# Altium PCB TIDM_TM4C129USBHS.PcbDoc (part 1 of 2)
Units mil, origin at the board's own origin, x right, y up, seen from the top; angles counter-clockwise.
Board outline 3900 x 3450 mil, 4 copper layers (Component Side, Ground Plane, Power Plane, Solder Side), stack 59.6 mil thick; 136 components, 129 nets, 585 pads, 295 vias.
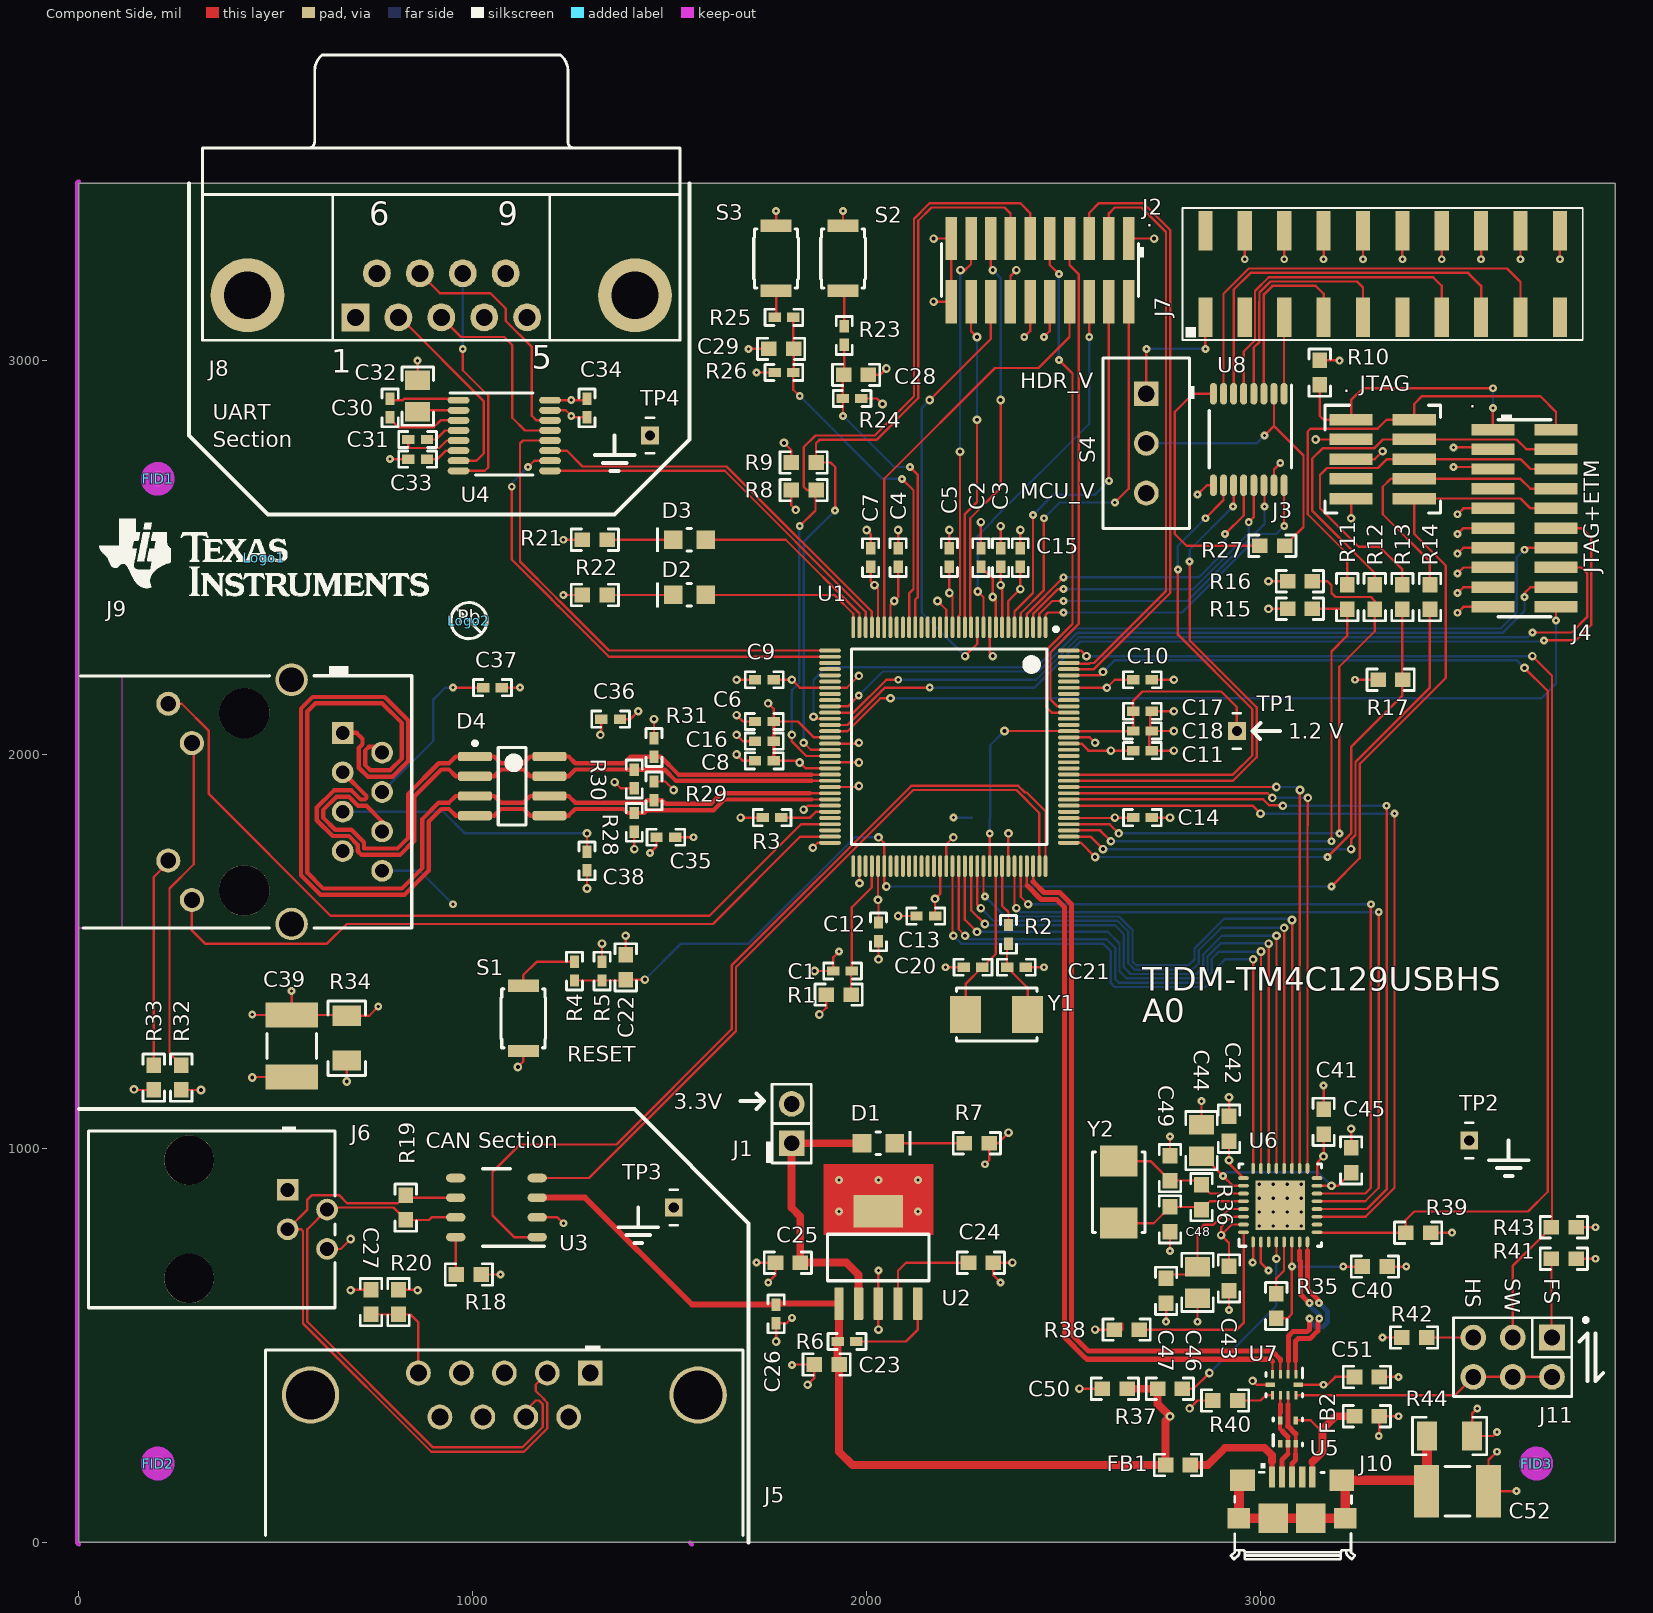
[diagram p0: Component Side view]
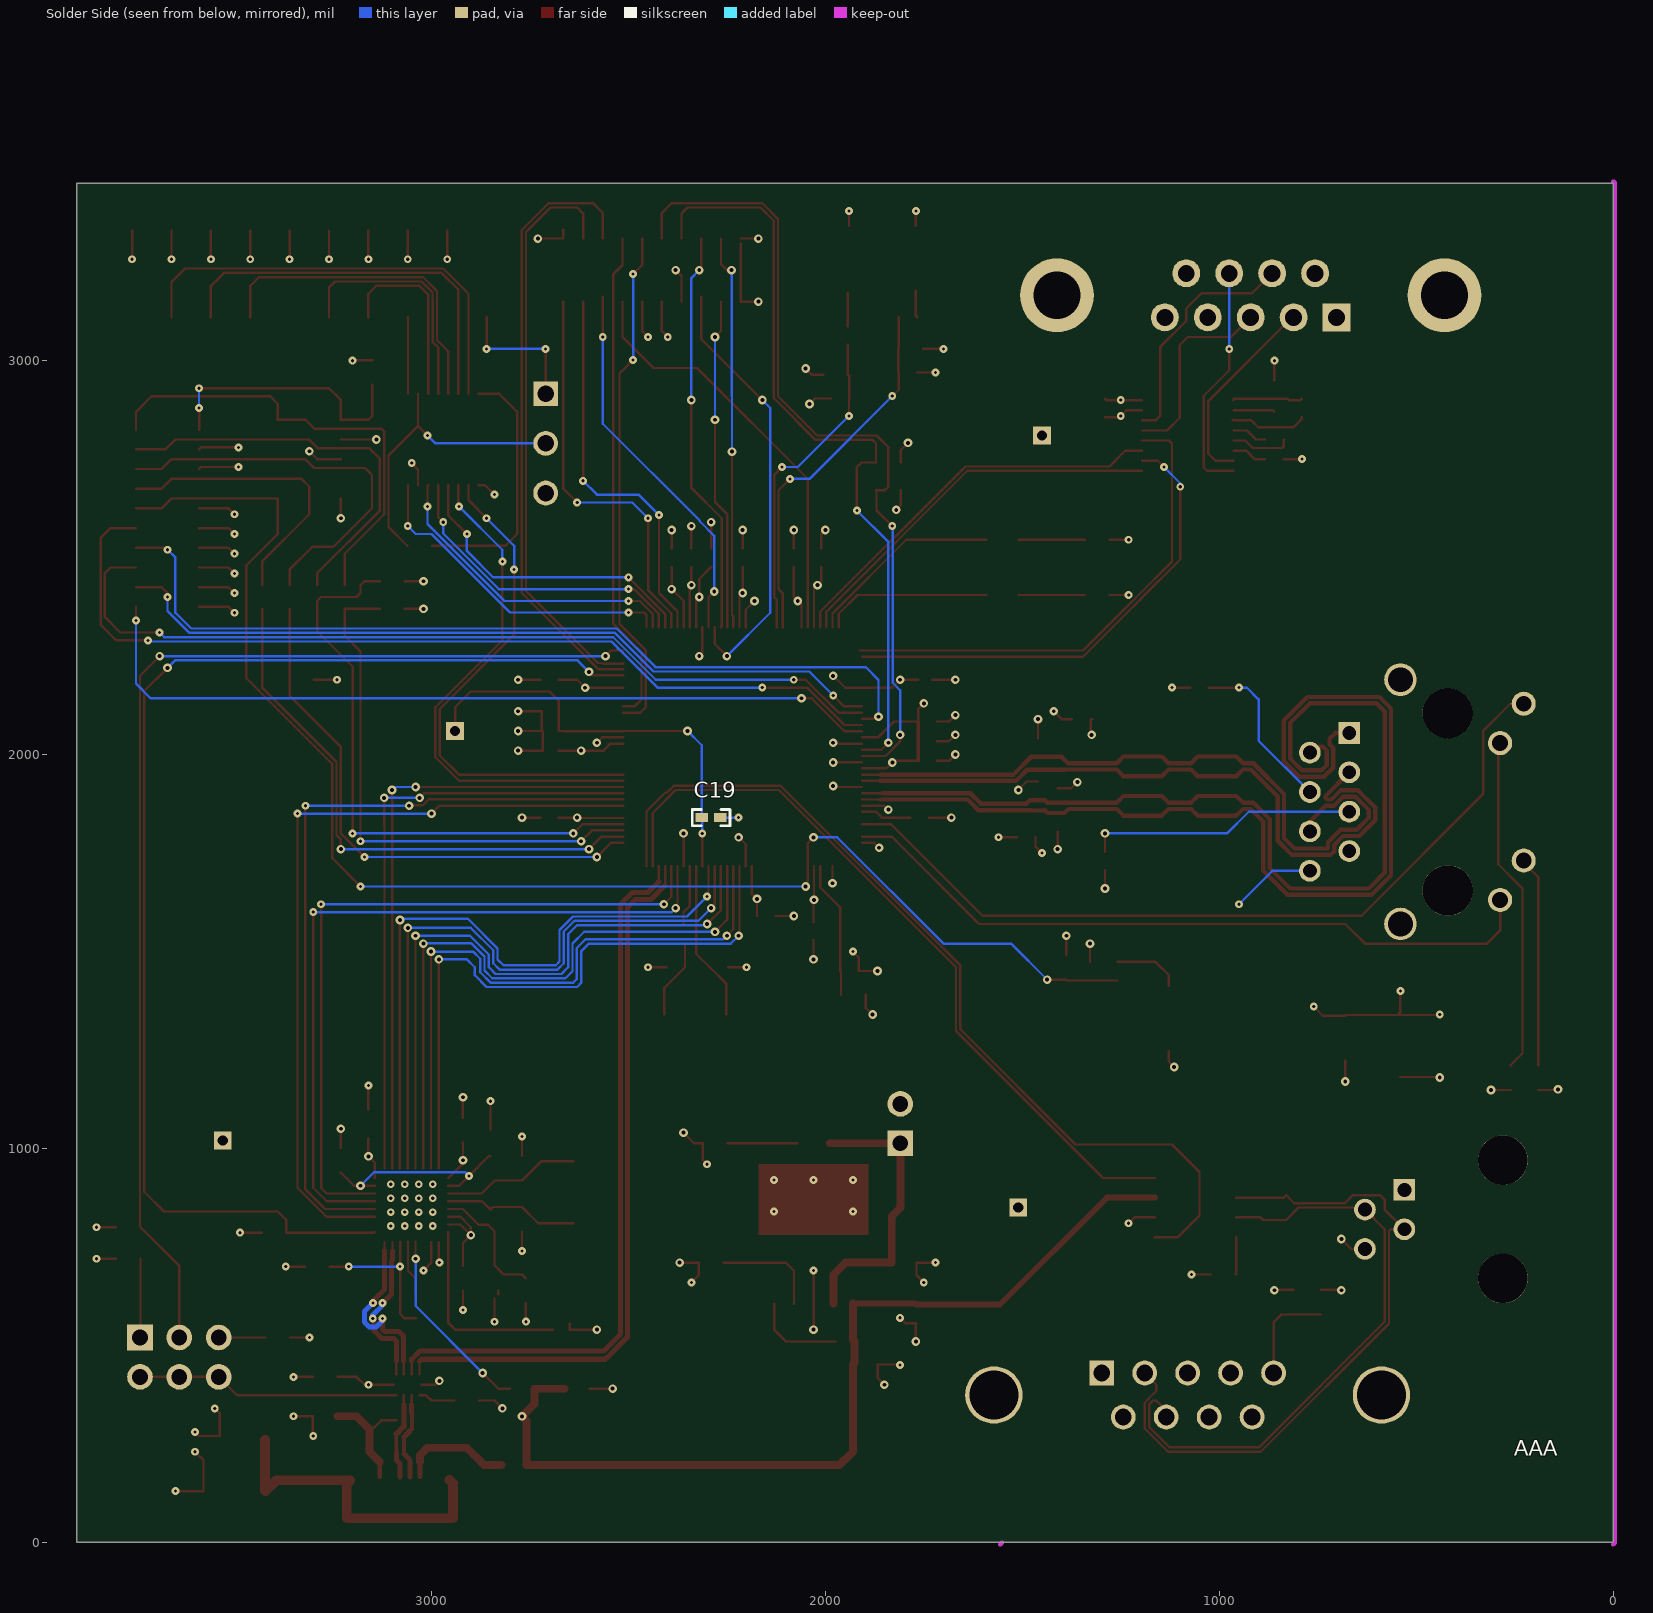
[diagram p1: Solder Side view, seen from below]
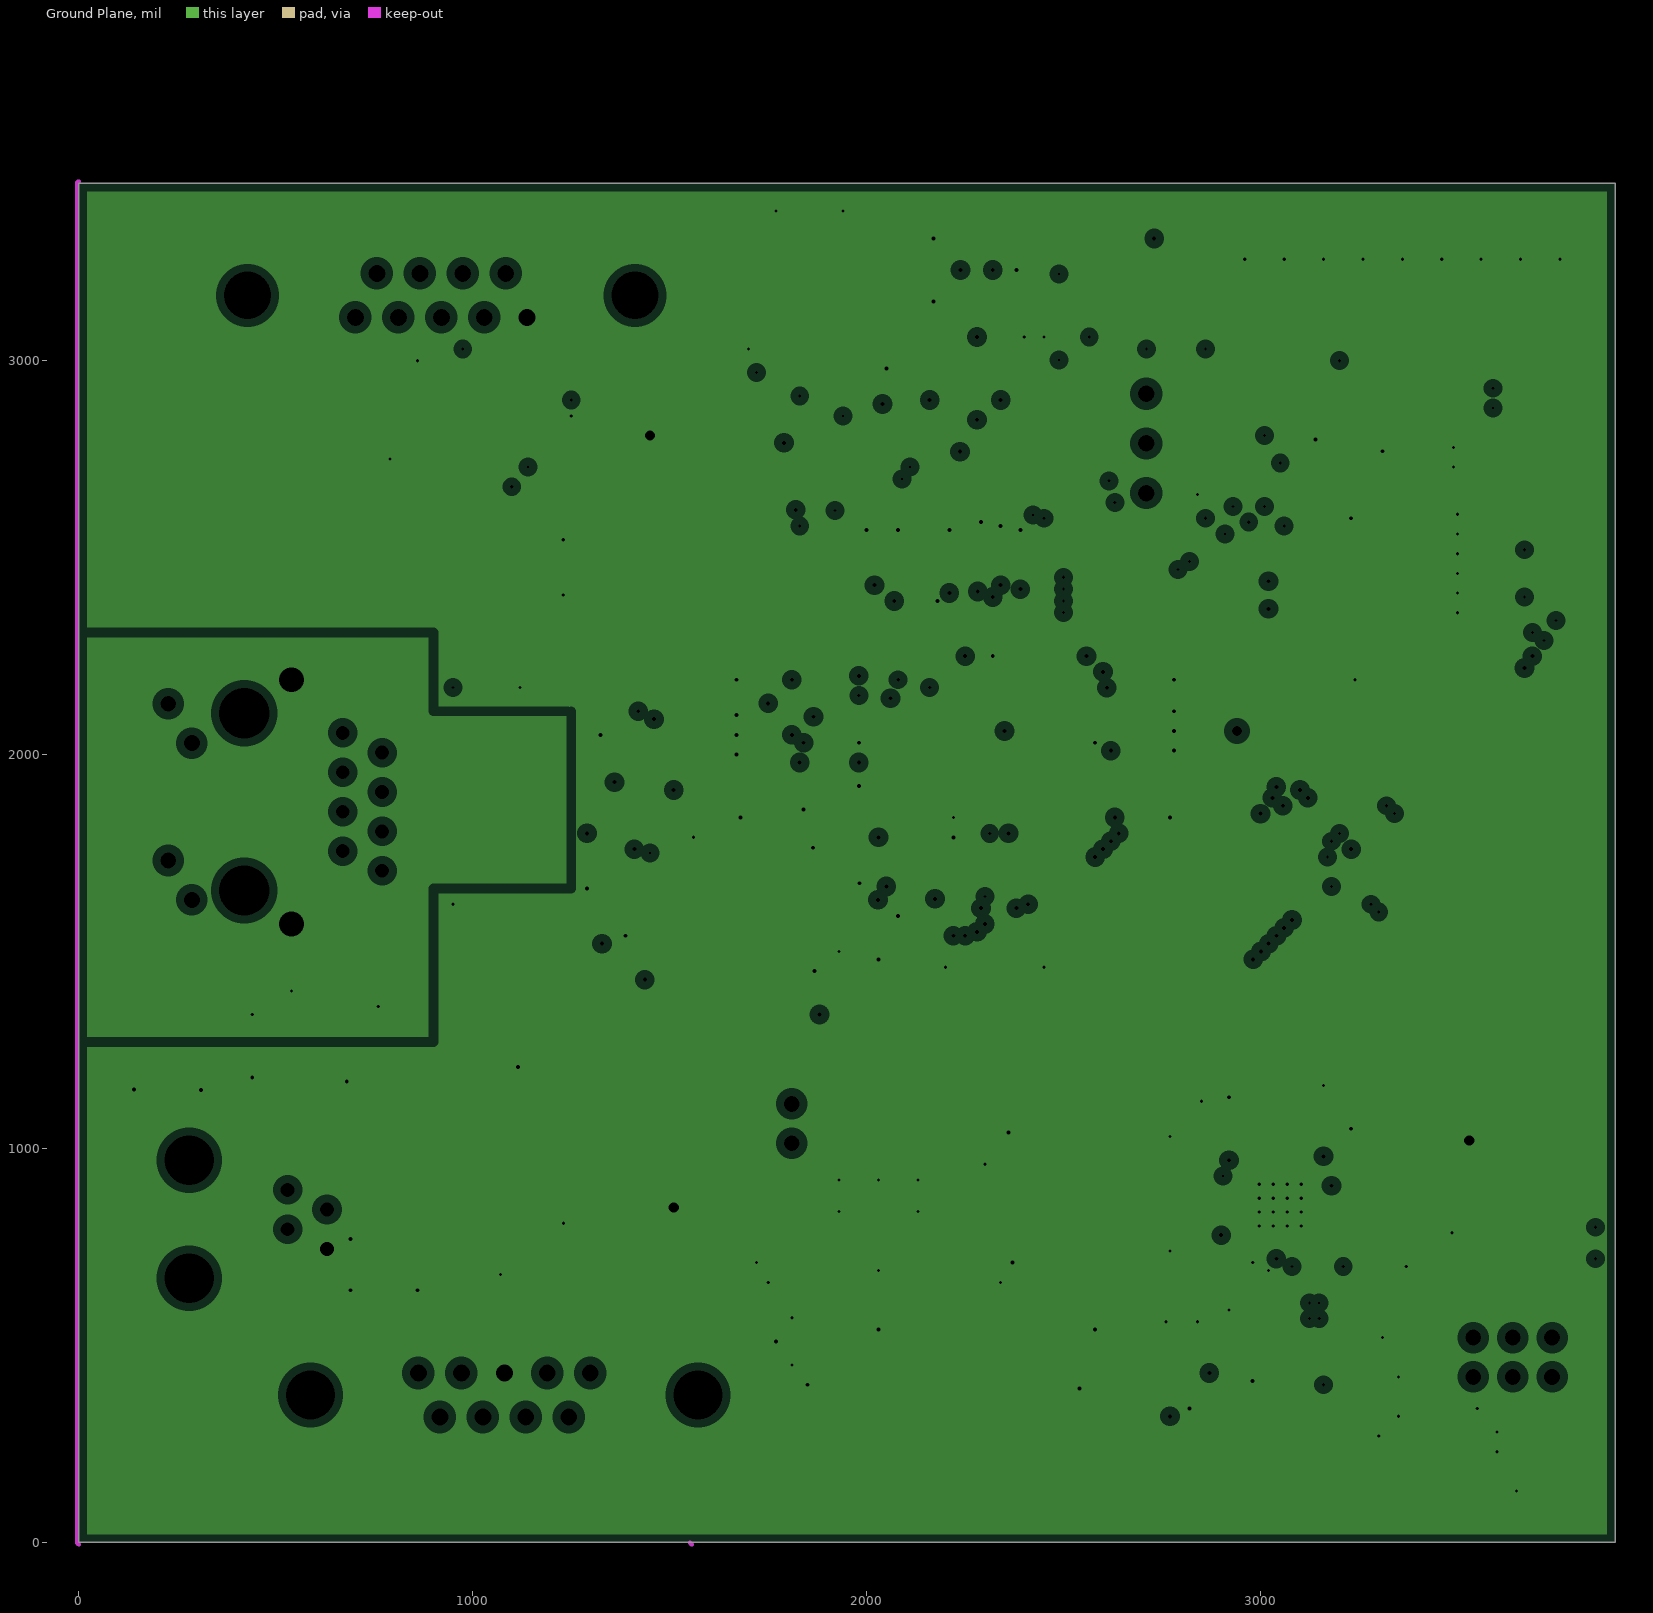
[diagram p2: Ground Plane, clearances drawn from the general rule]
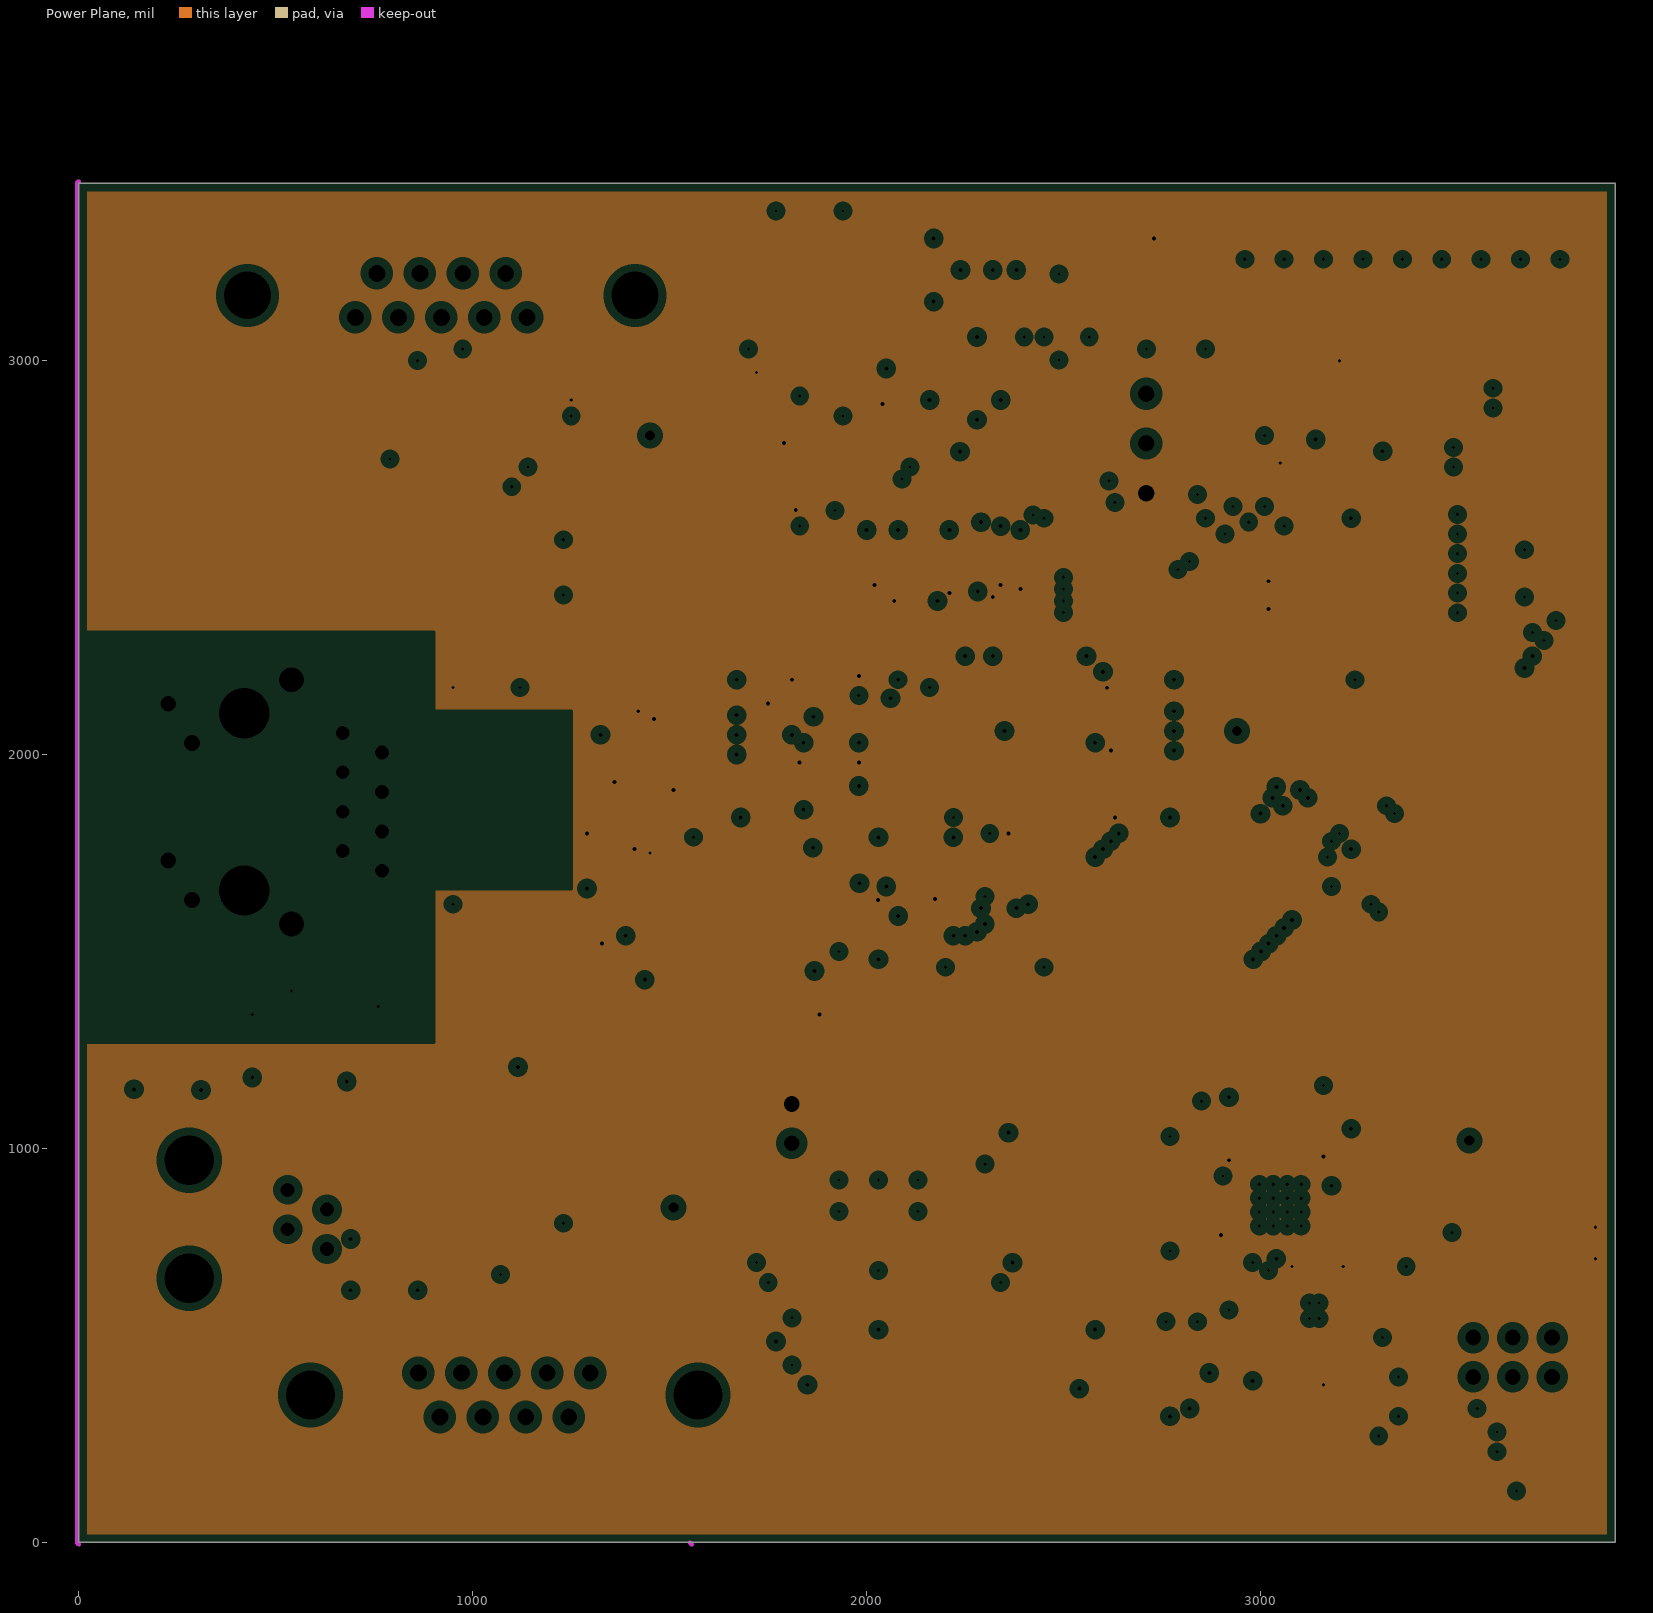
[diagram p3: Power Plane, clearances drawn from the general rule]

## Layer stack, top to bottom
Top Solder: solder mask 0.4, Solder Resist, Dk 3.5
Component Side: signal copper 1.4
Dielectric 1: core 13, FR-4, Dk 4.8
Ground Plane: plane copper 1.4, net (Multiple Nets)
Dielectric 3: prepreg 28, Dk 4.2
Power Plane: plane copper 1.4, net VCC_3P3
Dielectric 4: core 13, Dk 4.2
Solder Side: signal copper 1.4
Bottom Solder: solder mask 0.4, Solder Resist, Dk 3.5

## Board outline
0,0 0,3450 3900,3450 3900,0

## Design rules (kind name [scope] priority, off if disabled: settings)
AcuteAngle [All] p1: minimum=4.50000000000000E+0001 checktracksonly=FALSE
AssemblyTestPointUsage [All] p1: valid=2
Clearance Clearance_Pwr2GndVia [(IsVia AND (InNet('GND') OR InNet('VCC_3P3'))) vs (IsVia AND (InNet('GND') OR InNet('VCC_3P3')))] p1: gap=10
Clearance Clearance_Keepouts [((IsTrack Or IsArc) And Not InPoly) And IsFree and IsKeepOut vs ((IsTrack Or IsArc) And Not InPoly) And IsFree and IsKeepOut] p2: gap=0
Clearance Clearance_BoardEdge_MountingHoles [OnCopper and InComponentClass('Mounting Holes') vs IsKeepOut] p3: gap=40
Clearance Clearance_BoardEdge_Poly [OnCopper and InPoly vs IsKeepOut] p4: gap=25
Clearance Clearance_BoardEdge [OnCopper and Not InComponentClass('Logo') and not InComponentClass('FiducialMark') and not InRegion(1000,500,4000,800) and Not IsKeepout vs IsKeepOut] p5: gap=20
Clearance Clearance_Poly [InPolygon] p6: gap=10
Clearance [All] p7: gap=5
ComponentClearance ComponentClearance_MountingHoles_FiducialMarks [InComponentClass('Mounting Holes') vs InComponentClass('FiducialMark')] p1: gap=50 collisioncheckmode=3 verticalgap=10 showdistances=FALSE
ComponentClearance ComponentClearance_Shunt [InComponentClass('Header') vs InComponentClass('Shunt')] p2: gap=0 collisioncheckmode=3 verticalgap=0 showdistances=FALSE
ComponentClearance ComponentClearance_Logo [InComponentClass('Logo')] p3: gap=50 collisioncheckmode=3 verticalgap=10 showdistances=FALSE
ComponentClearance ComponentClearance_ScrewToNut [(HasFootprint('NY PMS 440 0025 PH')) vs (HasFootprint('Keystone_1902C'))] p4: gap=5 collisioncheckmode=3 verticalgap=10 showdistances=FALSE
ComponentClearance ComponentClearance_MountingHoles [InComponentClass('Mounting Holes')] p5: gap=250 collisioncheckmode=3 verticalgap=100000 showdistances=FALSE
ComponentClearance ComponentClearance_SmallPassives [HasFootprint('0201*') or HasFootprint('0402*') or HasFootprint('0508') or HasFootprint('0603*') or HasFootprint('0612') or HasFootprint('0805*') or HasFootprint('0815*') or HasFootprint('0830*') or HasFootprint('1206*') or HasFootprint('1210*') or HasFootprint('1808*') or HasFootprint('1812*') or HasFootprint('1825*') or HasFootprint('2010*') or HasFootprint('2220*') or HasFootprint('2225*') or HasFootprint('2512*') or HasFootprint('2728*') or HasFootprint('3518*') vs HasFootprint('0201*') or HasFootprint('0402*') or HasFootprint('0508') or HasFootprint('0603*') or HasFootprint('0612') or HasFootprint('0805*') or HasFootprint('0815*') or HasFootprint('0830*') or HasFootprint('1206*') or HasFootprint('1210*') or HasFootprint('1808*') or HasFootprint('1812*') or HasFootprint('1825*') or HasFootprint('2010*') or HasFootprint('2220*') or HasFootprint('2225*') or HasFootprint('2512*') or HasFootprint('2728*') or HasFootprint('3518*')] p6: gap=20 collisioncheckmode=3 verticalgap=10 showdistances=FALSE
ComponentClearance ComponentClearance_THtoSMT [IsThruComponent vs IsSMTComponent] p7: gap=40 collisioncheckmode=3 verticalgap=30 showdistances=FALSE
ComponentClearance ComponentClearance_THtoTH [IsThruComponent vs IsThruComponent] p8: gap=40 collisioncheckmode=3 verticalgap=30 showdistances=FALSE
ComponentClearance [All] p9: gap=40 collisioncheckmode=3 verticalgap=10 showdistances=FALSE
DiffPairsRouting DiffPairsRoutingUSB [(InNet('USBCONN_N') OR InNet('USBCONN_P') OR InNet('USBD_N') OR InNet('USBD_P') OR InNet('USBHS_N') OR InNet('USBHS_P'))] p1: maxlimit=50 minlimit=5 mostfreqgap=5 toplayer_minwidth=5 toplayer_maxwidth=14 toplayer_prefwidth=12.8 bottomlayer_minwidth=5 bottomlayer_maxwidth=14 bottomlayer_prefwidth=12.8 maxuncoupledlength=500
DiffPairsRouting DiffPairsRoutingEPHY [(InNet('EPHYRX_N') OR InNet('EPHYRX_P') OR InNet('EPHYtX_N') OR InNet('EPHYTX_P'))] p2: maxlimit=50 minlimit=5 mostfreqgap=5 toplayer_minwidth=6 toplayer_maxwidth=14 toplayer_prefwidth=11 bottomlayer_minwidth=6 bottomlayer_maxwidth=14 bottomlayer_prefwidth=11 maxuncoupledlength=500
FabricationTestPointUsage TestPointUsage [All] p1: valid=2 allowmultiple=FALSE
FabricationTestpoint Testpoint [All] p1: side=3 testpointundercomponent=TRUE minsize=40 maxsize=100 preferedsize=60 minholesize=0 maxholesize=40 preferedholesize=32 testpointgrid=1 allowsidetop=TRUE allowsidebottom=TRUE usegrid=TRUE gridtolerance=0.01
FanoutControl Fanout_LCC [IsLCC] p1: bgadir=Out bgaviamode=Centered fanoutstyle=Auto fanoutdirection=Alternating viagrid=1 // Fanout_LCC (Default Rule)
FanoutControl Fanout_BGA [IsBGA] p2: bgadir=Out bgaviamode=Centered fanoutstyle=Auto fanoutdirection=Alternating viagrid=1 // Fanout_BGA (Default Rule)
FanoutControl Fanout_Default [All] p4: bgadir=Out bgaviamode=Centered fanoutstyle=Auto fanoutdirection=Alternating viagrid=1 // Fanout_Default (Default Rule)
FanoutControl Fanout_Small [(CompPinCount < 5)] p5: bgadir=Out bgaviamode=Centered fanoutstyle=Auto fanoutdirection=OutThenIn viagrid=1 // Fanout_Small (Default Rule)
HoleSize [All] p1: absolutevalues=TRUE maxlimit=251 minlimit=8 maxpercent=80.000 minpercent=20.000
MatchedLengths MatchedLengthsUSB [InNet('USBHS_*') OR InNet('USBCONN_*') OR InNet('USBD_*')] p1: tolerance=100 checknetsindiffpair=TRUE checkdiffpairvsdiffpair=FALSE checkothers=FALSE
MatchedLengths MatchedLengthsULPI [InNet('ULPI*')] p2: tolerance=500 checknetsindiffpair=TRUE checkdiffpairvsdiffpair=FALSE checkothers=TRUE
MinimumAnnularRing MinimumAnnularRing_ThermalPadVias [IsVia and InAnyComponent] p1: minimumring=5
MinimumAnnularRing [All] p2: minimumring=5
MinimumSolderMaskSliver MinimumSolderMaskSliver_Logo [InComponentClass('Logo') vs InComponentClass('Logo')] p1: minsoldermaskwidth=0.7
MinimumSolderMaskSliver [All] p2: minsoldermaskwidth=1.96
PlaneClearance [All] p1: clearance=20
PlaneConnect [(InComponent('J1') OR InComponent('J5') OR InComponent('J6') OR InComponent('TP1'))] p1: planeconnectstyle=Relief reliefexpansion=13 reliefentries=4 reliefconductorwidth=10 reliefairgap=10
PlaneConnect PlaneConnectDirect [All] p2: planeconnectstyle=Direct reliefexpansion=20 reliefentries=4 reliefconductorwidth=10 reliefairgap=10
PolygonConnect [All] p1: connectstyle=Relief reliefconductorwidth=10 reliefentries=4 polygonreliefangle="90 Angle" airgapwidth=10
RoomDefinition RoomDefinitionU7 [HasFootprint('RSE0010A')] p1: confinementstyle=ConfineIn formatcopy=TRUE lockcomponents=FALSE outline 3120,350 3000,350 3000,460 3120,460
RoomDefinition RoomDefinitionU1 [HasFootprint('PDT0128A_N')] p2: confinementstyle=ConfineIn formatcopy=TRUE lockcomponents=FALSE outline 1860,1667.41 1860,2370 2560,2370 2560,1667.41
RoutingVias ThermalPadVias [IsVia and InAnyComponent] p1: holewidth=7.87 width=19.68 viastyle="Through Hole" minholewidth=7.87 minwidth=19.68 maxholewidth=12.99 maxwidth=23.62
RoutingVias [All] p2: holewidth=8 width=20 viastyle="Through Hole" minholewidth=8 minwidth=20 maxholewidth=15 maxwidth=27
SMDNeckDown [All] p1: percent=85.000
SilkToBoardRegionClearance [Not ((IsComment or IsDesignator) And (Hide <> 'False')) and not InRegion(1000,500,4000,800)] p1:
SilkToSilkClearance SilkToSilkClearance_Pb-FreeLogo [(HasFootprint('Pb-Free_Overlay_Medium') OR HasFootprint('Pb-Free_Overlay_Small')) vs (HasFootprint('Pb-Free_Overlay_Medium') OR HasFootprint('Pb-Free_Overlay_Small'))] p1: silktosilkclearance=0
SilkToSilkClearance [All] p2: silktosilkclearance=4
SilkToSolderMaskClearance SilkToComonentPadClearance [IsPad and InAnycomponent] p1: minsilkscreentomaskgap=5 clearancetoexposedcopper=TRUE
SilkToSolderMaskClearance "Silk to Solder Mask Opening" [All] p2: minsilkscreentomaskgap=4 clearancetoexposedcopper=FALSE
SolderMaskExpansion SolderMaskPlatedHoles [IsVia] p1: expansion=-20
SolderMaskExpansion [All] p2: expansion=1.97
UnpouredPolygon [All] p1: allowunpoured=FALSE
Width WidthUSBPower [(InNet('U_GND') OR InNet('U_VBUS') OR InNet('VCC_5P0') OR InNet('NetC25_1'))] p1: maxlimit=100 minlimit=6 preferedwidth=20
Width WidthShield [InNet('U_SHIELD')] p2: maxlimit=40 minlimit=10 preferedwidth=25
Width WidthRoom [TouchesRoom('RoomDefinitionU1') OR  TouchesRoom('RoomDefinitionU6') OR TouchesRoom('RoomDefinitionU7')] p3: maxlimit=14 minlimit=6 preferedwidth=6
Width [All] p4: maxlimit=12 minlimit=6 preferedwidth=6 checkconnectedcopper=TRUE
13 further rules are at their usual default settings.

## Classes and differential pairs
component class TIDM_TM4C129USBHS_USB: C40 C41 C42 C43 C44 C45 C46 C47 C48 C49 C50 C51 C52 FB1 FB2 FID1 FID2 FID3 J10 J11 Logo1 Logo2 R35 R36 R37 R38 R39 R40 R41 R42 R43 R44 U5 U6 U7 Y2
component class TIDM_TM4C129USBHS_Micro: C1 C2 C3 C4 C5 C6 C7 C8 C9 C10 C11 C12 C13 C14 C15 C16 C17 C18 C19 C20 C21 C22 C23 C24 C25 D1 J1 R1 R2 R3 R4 R5 R6 R7 S1 TP1 TP2 TP3 TP4 U1 U2 Y1
component class TIDM_TM4C129USBHS_Ethernet: C35 C36 C37 C38 C39 D4 J9 R28 R29 R30 R31 R32 R33 R34
component class TIDM_TM4C129USBHS_Connector: C26 C27 C28 C29 C30 C31 C32 C33 C34 D2 D3 J2 J3 J4 J5 J6 J7 J8 R8 R9 R10 R11 R12 R13 R14 R15 R16 R17 R18 R19 R20 R21 R22 R23 R24 R25 R26 R27 S2 S3 S4 U3 U4 U8
component class Header: J1 J3 J7 J11
component class FiducialMark: FID1 FID2 FID3
component class Logo: Logo1
differential pair USBHS: +USBHS_P -USBHS_N
differential pair USBD: +USBD_P -USBD_N
differential pair USBCONN: +USBCONN_P -USBCONN_N
differential pair EPHYTX: +EPHYRX_P -EPHYRX_N
differential pair EPHYRX: +EPHYTX_P -EPHYTX_N

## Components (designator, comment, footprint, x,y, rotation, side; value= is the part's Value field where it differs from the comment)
C1 "GRM155R71C104KA88D" 0402 1938.78,1450.5 r180 top
C2 "C1005X5R1C105K050BC" 0402 2290,2500 r90 top
C3 "GRM155R71C104KA88D" 0402 2340,2500 r90 top
C4 "GRM155R71C104KA88D" 0402 2080,2500 r90 top
C5 "GRM155R71C104KA88D" 0402 2210,2500 r90 top
C6 "GRM155R71C104KA88D" 0402 1740,2084 r180 top
C7 "GRM155R71C104KA88D" 0402 2010,2500 r90 top
C8 "GRM155R71C104KA88D" 0402 1740,1984 r180 top
C9 "GRM155R71C104KA88D" 0402 1740,2190 r180 top
C10 "GRM155R71C104KA88D" 0402 2700,2190 r0 top
C11 "GRM155R71C104KA88D" 0402 2700,2010 r0 top
C12 "GRM155R71C104KA88D" 0402 2030,1550 r270 top
C13 "GRM155R71C104KA88D" 0402 2150,1590 r180 top
C14 "GRM155R71C104KA88D" 0402 2700,1840 r0 top
C15 "GRM155R71C103KA01D" 0402 2390,2500 r90 top
C16 "GRM155R71C103KA01D" 0402 1740,2034 r180 top
C17 "GRM155R61C225KE11D" 0402 2700,2110 r0 top
C18 "C1005X5R1C105K050BC" 0402 2700,2060 r0 top
C19 "GRM155R71C104KA88D" 0402 2290,1840 r180 bottom
C20 "C1005C0G1H220J050BA" 0402 2270,1460 r180 top
C21 "C1005C0G1H220J050BA" 0402 2380,1460 r0 top
C22 "C0603C104J3RAC" 0603 1388.19,1460 r90 top
C23 "EMK107B7104KA-T" 0603 1898.5,451.5 r180 top
C24 "EMK107B7104KA-T" 0603 2290,710 r0 top
C25 "GRM188R61C225KE15D" 0603 1800,710 r180 top
C26 "GRM155R71C104KA88D" 0402 1770,580 r270 top
C27 "C0603X332K5RACTU" 0603 741.46,610 r90 top
C28 "C0603C104J3RAC" 0603 1973,2963.99 r0 top
C29 "C0603C104J3RAC" 0603 1783,3030 r180 top
C30 "C1005X5R0J104K" 0402 790,2880 r270 top
C31 "C1005X5R0J104K" 0402 860,2800 r180 top
C32 "08053C104KAT2A" 0805_HV 860,2910 r270 top
C33 "C1005X5R0J104K" 0402 860,2750 r180 top
C34 "C1005X5R0J104K" 0402 1290,2880 r270 top
C35 "GCM155R71C104KA55D" 0402 1490,1790 r0 top
C36 "GCM155R71C104KA55D" 0402 1350,2090 r180 top
C37 "GCM155R71C104KA55D" 0402 1050,2170 r0 top
C38 "GCM155R71C104KA55D" 0402 1290,1730 r270 top
C39 "1812GC472KA1" 1812 540,1260 r270 top
C40 "06035C104KAT2A" 0603 3290,700 r0 top
C41 "06035C104KAT2A" 0603 3160.2,1067.5 r90 top
C42 "06035C104KAT2A" 0603 2920,1050 r90 top
C43 "06035C104KAT2A" 0603 2920,670 r270 top
C44 "C2012X7R1A475M" 0805_HV 2850,1020 r90 top
C45 "06035C104KAT2A" 0603 3230,970 r90 top
C46 "C2012X7R1A475M" 0805_HV 2840,660 r270 top
C47 "06035C104KAT2A" 0603 2760.2,638.5 r270 top
C48 "06035A150JAT2A" 0603 2770,820 r270 top
C49 "06035A150JAT2A" 0603 2770,950 r90 top
C50 "GRM188R71A105KA61D" 0603 2630,390 r180 top
C51 "06035C104KAT2A" 0603 3270,420 r180 top
C52 "1812GC472KA1" 1812 3500,130 r0 top
D1 "QTLP630C4TR" QTLP630C_Green 2029.49,1013.08 r0 top
D2 "QTLP630C4TR" QTLP630C_Green 1549.83,2545.28 r180 top
D3 "QTLP630C4TR" QTLP630C_Green 1549.83,2405.28 r180 top
D4 "SLVU2.8-4.TBT" SO-8 1100,1920 r0 top
FB1 "BLM18AG121SN1D" 0603 2790.2,196.14 r0 top
FB2 "BLM18AG121SN1D" 0603 3270,320 r0 top
FID1 "Fiducial" Fiducial10-20 200,2700 r0 top
FID2 "Fiducial" Fiducial10-20 200,200 r0 top
FID3 "Fiducial" Fiducial10-20 3700,200 r0 top
J1 "TSW-102-07-G-S" TSW-102-07-G-S 1809.49,1063.08 r90 top
J2 "FTSH-110-01-L-DV-K" Samtec_FTSH-110-01-x-DV-K 2440,3230 r270 top
J3 "FTSH-105-01-F-DV" Samtec_FTSH-105-01-x-DV 3310,2750 r0 top
J4 "FTSH-110-01-L-DV-K" Samtec_FTSH-110-01-x-DV-K 3670,2600 r0 top
J5 "1734354-1" TE_1734354-1 1080,0 r270 top
J6 "A-2014-3-4-N-T-R" Assman_A-2014-3-x-N-T-R 280,820 r270 top
J7 "TSM-110-01-L-DV-P" CONN_TSM-110-01-T-DV-P 3310,3220 r0 top
J8 "182-009-213R171" NORCOMP_182-009-213R171 920,3540 r0 top
J9 "J0011D21BNL" Pulse_J0011D21BNL -5,1880 r270 top
J10 "1981568-1" TE_1981568-1 3080,0 r0 top
J11 "TSW-103-07-G-D" TSW-103-07-G-D 3640,470 r180 top
Logo1 "Texas Instruments" TI_Stacked_Overlay_Small 470,2500 r0 top
Logo2 "Pb-Free Symbol" Pb-Free_Overlay_Small 990,2340 r0 top
R1 "CRCW060351R0JNEA" 0603 1928.78,1390.5 r0 top
R2 "ERJ-2GE0R00X" 0402 2360,1543.62 r270 top
R3 "CRCW04024K87FKED" 0402 1760,1840 r0 top
R4 "CRCW0402100RJNED" 0402 1258.19,1450 r90 top
R5 "CRCW040210K0JNED" 0402 1328.19,1450 r90 top
R6 "ERJ-2RKF1003X" 0402 1950,510 r0 top
R7 "RC0603JR-07330RL" 0603 2279.49,1013.08 r0 top
R8 "CRCW06034K70JNEA" 0603 1840,2671.46 r180 top
R9 "CRCW06034K70JNEA" 0603 1840,2741.46 r180 top
R10 "CRCW0603100RJNEA" 0603 3150,2970 r270 top
R11 "CRCW060333R0JNEA" 0603 3220,2400 r270 top
R12 "CRCW060333R0JNEA" 0603 3290,2400 r270 top
R13 "CRCW060333R0JNEA" 0603 3360,2400 r270 top
R14 "CRCW060333R0JNEA" 0603 3430,2400 r270 top
R15 "CRCW060310K0JNEA" 0603 3100,2370 r180 top
R16 "CRCW060310K0JNEA" 0603 3100,2440 r180 top
R17 "CRCW060310K0JNEA" 0603 3330,2190 r0 top
R18 "CRCW060310K0JNEA" 0603 990,680 r180 top
R19 "RC0603FR-07120RL" 0603 830,850 r90 top
R20 "CRCW06031M00JNEA" 0603 811.46,610 r270 top
R21 "RC0603JR-07330RL" 0603 1309.83,2545.28 r180 top
R22 "RC0603JR-07330RL" 0603 1309.83,2405.28 r180 top
R23 "CRCW0402100RJNED" 0402 1943,3063.99 r90 top
R24 "CRCW040210K0JNED" 0402 1963,2903.99 r0 top
R25 "CRCW0402100RJNED" 0402 1790,3110 r180 top
R26 "CRCW040210K0JNED" 0402 1790,2970 r180 top
R27 "CRCW060310K0JNEA" 0603 3030,2530 r0 top
R28 "CRCW040249R9FKED" 0402 1410,1828 r270 top
R29 "CRCW040249R9FKED" 0402 1460,1908 r90 top
R30 "CRCW040249R9FKED" 0402 1410,1938 r270 top
R31 "CRCW040249R9FKED" 0402 1460,2018 r90 top
R32 "RC0603JR-07330RL" 0603 260,1180 r270 top
R33 "RC0603JR-07330RL" 0603 190,1180 r270 top
R34 "CRCW12061M00JNEA" 1206 680,1280 r90 top
R35 "RCG060310K0FKEA" 0603 3040,600 r270 top
R36 "CRCW06031M00JNEA" 0603 2850.2,876.14 r270 top
R37 "RC0603FR-07820RL" 0603 2770,390 r180 top
R38 "RC0603FR-0712KL" 0603 2660,540 r0 top
R39 "RCG060310K0FKEA" 0603 3400.2,786.14 r180 top
R40 "RC0603JR-0710KL" 0603 2910,360 r0 top
R41 "RC0603JR-0710KL" 0603 3770,720 r0 top
R42 "RC0603JR-0710KL" 0603 3390,520 r180 top
R43 "RC0603JR-0710KL" 0603 3770,800 r0 top
R44 "CRCW12061M00JNEA" 1206 3480,270 r180 top
S1 "SKRKAEE010" SW_SKRKAEE010 1128.19,1330 r90 top
S2 "SKRKAEE010" SW_SKRKAEE010 1940,3260 r270 top
S3 "SKRKAEE010" SW_SKRKAEE010 1770,3260 r270 top
S4 "1825115-1" SW_1825115-1 2710,2790 r270 top
TP1 "TMS-101-02-T-S" SAMTEC_TMS-101-02-T-S 2940,2060 r180 top
TP2 "TMS-101-02-T-S" SAMTEC_TMS-101-02-T-S 3530,1020 r0 top
TP3 "TMS-101-02-T-S" SAMTEC_TMS-101-02-T-S 1510,850 r0 top
TP4 "TMS-101-02-T-S" SAMTEC_TMS-101-02-T-S 1450,2810 r0 top
U1 "TM4C129ENCPDTI3R" PDT0128A_N 2210,2020 r270 top
U2 "TPS73733DCQR" DCQ0006A_N 2029.49,723.08 r90 top
U3 "SN65HVD1050D" D0008A_L 1060,850 r180 top
U4 "MAX3232CPW" PW0016A_N 1080,2810 r0 top
U5 "TPD2E2U06DRLR" DRL0005A 3069.53,280 r90 top
U6 "USB3300-EZK" Microchip_32QFN-3304-5x5B 3050,856 r90 top
U7 "TS3USB221ERSER" RSE0010A 3060,400 r270 top
U8 "TXB0106PWR" PW0016A_N 2970,2800 r270 top
Y1 "NX5032GA-25.000M-STD-CSK-4" NDK_NX5032GA 2330,1340 r180 top
Y2 "NX5032GA-24.000M-STD-CSK-4" NDK_NX5032GA 2640,889 r90 top

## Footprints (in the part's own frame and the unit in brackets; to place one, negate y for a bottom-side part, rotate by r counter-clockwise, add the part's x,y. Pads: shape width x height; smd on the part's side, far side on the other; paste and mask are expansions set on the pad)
0402 [mm] "0402 from SM-752 data"
  rect 0.8x0.6 smd: 1(-0.6,0) 2(0.6,0)
  silkscreen extent -1.22,-0.52 1.22,0.52, body extent -0.55,-0.3 0.55,0.3, height 0.6
0603 [mm] "0603 from SM-752 data"
  rect 1x0.95 smd: 1(-0.8,0) 2(0.8,0)
  silkscreen extent -1.52,-0.69 1.52,0.69, body extent -0.87,-0.47 0.87,0.47, height 1
0805_HV [mil] "0805 with 30mil clearance between pads"
  rect 50x63 smd: 1(-40,0) 2(40,0)
  silkscreen extent -74,-40 74,40, body extent -43,-29 43,29, height 57
1206 [mm] "1206 from SM-752 data"
  rect 1.3x1.85 smd: 1(-1.45,0) 2(1.45,0)
  silkscreen extent -2.4,-1.21 2.4,1.21, body extent -1.7,-0.9 1.7,0.9, height 1.35
1812 [mm]
  rect 1.6x3.4 smd: 1(-2,0) 2(2,0)
  silkscreen extent -0.8,-1.6 0.8,1.6, body extent -2.4,-1.7 2.4,1.7, height 1.35
Assman_A-2014-3-x-N-T-R [mm] "TH, 4-Leads, Body 15.9x11.4mm"
  rect 1.4x1.4 hole 0.9: 1(-1.9,6.35)
  round 1.4 hole 0.9: 2(-0.63,8.89) 3(0.64,6.35) 4(1.91,8.89)
  round 3.2 hole 3.2: ""(-3.81,0) ""(3.81,0)
  silkscreen extent -6,-6.5 5.7,9.4, body extent -5.7,-6.5 5.7,9.4, height 16.3
CONN_TSM-110-01-T-DV-P [mil]
  rect 36x100 smd: 1(-450,-110) 2(-450,110) 3(-350,-110) 4(-350,110) 5(-250,-110) 6(-250,110) 7(-150,-110) 8(-150,110) 9(-50,-110) 10(-50,110) 11(50,-110) 12(50,110) 13(150,-110) 14(150,110) 15(250,-110) 16(250,110) 17(350,-110) 18(350,110) 19(450,-110) 20(450,110)
  silkscreen extent -508,-168 508,168, body extent -500,-145 500,145, height 380
D0008A_L [mm] "SOIC, 8-Leads, Body 4.9x3.9mm, Pitch 1.27mm, IPC High Density"
  oval 1.25x0.55 smd: 1(-2.625,1.905) 2(-2.625,0.635) 3(-2.625,-0.635) 4(-2.625,-1.905) 5(2.625,-1.905) 6(2.625,-0.635) 7(2.625,0.635) 8(2.625,1.905)
  silkscreen extent -3.1,-2.5 0.9,2.5, body extent -3,-2.45 3,2.45, height 1.63
DCQ0006A_N [mm] "SOT223, 6-Leads, Body 6.6x7.3mm (max), Pitch 1.27mm, IPC Medium Density"
  rrect17% 2.1x0.6 smd: 1(-2.975,2.54) 2(-2.975,1.27) 3(-2.975,0) 4(-2.975,-1.27) 5(-2.975,-2.54)
  rrect5% 2.1x3.2 smd: 6(2.975,0)
  silkscreen extent -1.5,-3.27 1.5,3.28, body extent -3.54,-3.25 3.54,3.25, height 1.8
DRL0005A [mm] "SOTFL, 5-Flat Leads, Body 1.2x1.6x0.6mm, Pitch 0.5mm, TI recommended"
  rect 0.5x0.3 smd: 1(-0.75,0.5) 2(-0.75,0) 3(-0.75,-0.5) 4(0.75,-0.5) 5(0.75,0.5)
  silkscreen extent -0.9,-0.95 0.9,0.95, body extent -0.85,-0.85 0.85,0.85, height 0.62
Fiducial10-20 [mm]
  round 1 smd mask+0.5: 1(0,0)
  Component Side keep-out circle w1.178: c0,0 r0.5
Microchip_32QFN-3304-5x5B [mm] "QFN, 32-Leads, Body 5x5mm, Pitch 0.5mm"
  rrect100% 0.69x0.24 smd paste-0.5 mask+0.092: 1(-2.37,1.75)
  rrect100% 0.69x0.24 smd paste-0.69 mask+0.092: 2(-2.37,1.25) 3(-2.37,0.75) 4(-2.37,0.25) 5(-2.37,-0.25) 6(-2.37,-0.75) 7(-2.37,-1.25) 8(-2.37,-1.75) 17(2.37,-1.75) 18(2.37,-1.25) 19(2.37,-0.75) 20(2.37,-0.25) 21(2.37,0.25) 22(2.37,0.75) 23(2.37,1.25) 24(2.37,1.75)
  rrect100% 0.24x0.69 smd paste-0.69 mask+0.092: 9(-1.75,-2.37) 10(-1.25,-2.37) 11(-0.75,-2.37) 12(-0.25,-2.37) 13(0.25,-2.37) 14(0.75,-2.37) 15(1.25,-2.37) 16(1.75,-2.37) 25(1.75,2.37) 26(1.25,2.37) 27(0.75,2.37) 28(0.25,2.37) 29(-0.25,2.37) 30(-0.75,2.37) 31(-1.25,2.37) 32(-1.75,2.37)
  rrect3% 3.2x3.2 smd paste-3.2: 33(0,0)
  silkscreen extent -2.65,-2.65 2.65,2.65, body extent -2.55,-2.55 2.55,2.55, height 1.01
NDK_NX5032GA [mm] "SMD, 2-Leads Body 5x3.2mm"
  rect 2x2.4 smd: 1(-2,0) 2(2,0)
  silkscreen extent -2.6,-1.7 2.6,1.7, body extent -2.6,-1.7 2.6,1.7, height 1.5
NORCOMP_182-009-213R171 [mm] "Connector; D Subminiature 9 Position; Right Angle"
  rect 1.8x1.8 hole 1.092: 1(-5.54,-10.92)
  round 1.8 hole 1.092: 2(-2.77,-10.92) 3(0,-10.92) 4(2.77,-10.92) 5(5.54,-10.92) 6(-4.155,-8.08) 7(-1.385,-8.08) 8(1.385,-8.08) 9(4.155,-8.08)
  round 4.76 hole 3.05: 10(-12.495,-9.5) 11(12.495,-9.5)
  silkscreen extent -15.4,-12.4 15.4,6, body extent -15.41,-12.98 15.41,6.1, height 12.55
Pb-Free_Overlay_Small [mil]
  silkscreen extent -46,-46 46,46
PDT0128A_N [mm] "Thin QFP, 128-Leads, Body 14x14mm, Pitch 0.4mm, IPC Medium Density"
  oval 1.4x0.25 smd: 1(-7.7,6.2) 2(-7.7,5.8) 3(-7.7,5.4) 4(-7.7,5) 5(-7.7,4.6) 6(-7.7,4.2) 7(-7.7,3.8) 8(-7.7,3.4) 9(-7.7,3) 10(-7.7,2.6) 11(-7.7,2.2) 12(-7.7,1.8) 13(-7.7,1.4) 14(-7.7,1) 15(-7.7,0.6) 16(-7.7,0.2) 17(-7.7,-0.2) 18(-7.7,-0.6) 19(-7.7,-1) 20(-7.7,-1.4) 21(-7.7,-1.8) 22(-7.7,-2.2) 23(-7.7,-2.6) 24(-7.7,-3) 25(-7.7,-3.4) 26(-7.7,-3.8) 27(-7.7,-4.2) 28(-7.7,-4.6) 29(-7.7,-5) 30(-7.7,-5.4) 31(-7.7,-5.8) 32(-7.7,-6.2) 65(7.7,-6.2) 66(7.7,-5.8) 67(7.7,-5.4) 68(7.7,-5) 69(7.7,-4.6) 70(7.7,-4.2) 71(7.7,-3.8) 72(7.7,-3.4) 73(7.7,-3) 74(7.7,-2.6) 75(7.7,-2.2) 76(7.7,-1.8) 77(7.7,-1.4) 78(7.7,-1) 79(7.7,-0.6) 80(7.7,-0.2) 81(7.7,0.2) 82(7.7,0.6) 83(7.7,1) 84(7.7,1.4) 85(7.7,1.8) 86(7.7,2.2) 87(7.7,2.6) 88(7.7,3) 89(7.7,3.4) 90(7.7,3.8) 91(7.7,4.2) 92(7.7,4.6) 93(7.7,5) 94(7.7,5.4) 95(7.7,5.8) 96(7.7,6.2)
  oval 0.25x1.4 smd: 33(-6.2,-7.7) 34(-5.8,-7.7) 35(-5.4,-7.7) 36(-5,-7.7) 37(-4.6,-7.7) 38(-4.2,-7.7) 39(-3.8,-7.7) 40(-3.4,-7.7) 41(-3,-7.7) 42(-2.6,-7.7) 43(-2.2,-7.7) 44(-1.8,-7.7) 45(-1.4,-7.7) 46(-1,-7.7) 47(-0.6,-7.7) 48(-0.2,-7.7) 49(0.2,-7.7) 50(0.6,-7.7) 51(1,-7.7) 52(1.4,-7.7) 53(1.8,-7.7) 54(2.2,-7.7) 55(2.6,-7.7) 56(3,-7.7) 57(3.4,-7.7) 58(3.8,-7.7) 59(4.2,-7.7) 60(4.6,-7.7) 61(5,-7.7) 62(5.4,-7.7) 63(5.8,-7.7) 64(6.2,-7.7) 97(6.2,7.7) 98(5.8,7.7) 99(5.4,7.7) 100(5,7.7) 101(4.6,7.7) 102(4.2,7.7) 103(3.8,7.7) 104(3.4,7.7) 105(3,7.7) 106(2.6,7.7) 107(2.2,7.7) 108(1.8,7.7) 109(1.4,7.7) 110(1,7.7) 111(0.6,7.7) 112(0.2,7.7) 113(-0.2,7.7) 114(-0.6,7.7) 115(-1,7.7) 116(-1.4,7.7) 117(-1.8,7.7) 118(-2.2,7.7) 119(-2.6,7.7) 120(-3,7.7) 121(-3.4,7.7) 122(-3.8,7.7) 123(-4.2,7.7) 124(-4.6,7.7) 125(-5,7.7) 126(-5.4,7.7) 127(-5.8,7.7) 128(-6.2,7.7)
  silkscreen extent -7.7,-6.3 6.3,7, body extent -8,-8 8,8, height 1.07
Pulse_J0011D21BNL [mm] "Connector, RJ-45 with integrated magnetics, 1x1, R/A, TH"
  rect 1.4x1.4 hole 0.89: 1(-4.445,17.14)
  round 1.4 hole 0.89: 2(-3.175,19.68) 3(-1.905,17.14) 4(-0.635,19.68) 5(0.635,17.14) 6(1.905,19.68) 7(3.175,17.14) 8(4.445,19.68)
  round 1.55 hole 1.02: 9(-6.325,5.89) 10(-3.785,7.41) 11(3.785,5.89) 12(6.325,7.41)
  round 2.1 hole 1.6: 13(-7.875,13.84) 14(7.875,13.84)
  round 3.25 hole 3.25: MH1(-5.715,10.79) MH2(5.715,10.79)
  Component Side keep-out region: -8.13,0 8.13,0 8.13,2.92 -8.13,2.92
  silkscreen extent -8.75,0.23 8.13,21.59, body extent -8.13,0 8.13,21.59, height 13.84
PW0016A_N [mm] "TSOP, 16-Leads, Body 5x4.4mm, Pitch 0.65mm, IPC Medium Density"
  oval 1.4x0.45 smd: 1(-2.95,2.275) 2(-2.95,1.625) 3(-2.95,0.975) 4(-2.95,0.325) 5(-2.95,-0.325) 6(-2.95,-0.975) 7(-2.95,-1.625) 8(-2.95,-2.275) 9(2.95,-2.275) 10(2.95,-1.625) 11(2.95,-0.975) 12(2.95,-0.325) 13(2.95,0.325) 14(2.95,0.975) 15(2.95,1.625) 16(2.95,2.275)
  silkscreen extent -3.5,-2.55 1.85,2.75, body extent -3.21,-2.5 3.21,2.5, height 1
QTLP630C_Green [mm] "SMT, 2-Leads, Body 2x1.25mm"
  rect 1.2x1.2 smd: 1(-1.05,0) 2(1.05,0)
  silkscreen extent -0.15,-0.8 2.15,0.8, body extent -1.1,-0.73 1.1,0.73, height 1.22
RSE0010A [mm] "QFN, 10-Leads, Body 1.5x2mm, Pitch 0.5mm, TI Recommended"
  rect 0.55x0.2 smd: 1(-0.675,0.75) 2(-0.675,0.25) 3(-0.675,-0.25) 4(-0.675,-0.75) 6(0.675,-0.75) 7(0.675,-0.25) 8(0.675,0.25) 9(0.675,0.75)
  rect 0.3x0.6 smd: 5(0,-0.9) 10(0,0.9)
  silkscreen extent -1.07,-1.17 0.77,1.18, body extent -0.77,-1.02 0.78,1.03, height 0.61
Samtec_FTSH-105-01-x-DV [mm] "Header, 1.27mm, 5x2, SMT"
  rect 2.79x0.74 smd: 1(-2.035,2.54) 2(2.035,2.54) 3(-2.035,1.27) 4(2.035,1.27) 5(-2.035,0) 6(2.035,0) 7(-2.035,-1.27) 8(2.035,-1.27) 9(-2.035,-2.54) 10(2.035,-2.54)
  silkscreen extent -3.73,-3.48 3.73,3.48, body extent -2.92,-3.17 2.92,3.18, height 5.98
Samtec_FTSH-110-01-x-DV-K [mm] "Header (Shrouded), 1.27mm, 10x2, SMT"
  rect 2.79x0.74 smd: 1(-2.035,5.715) 2(2.035,5.715) 3(-2.035,4.445) 4(2.035,4.445) 5(-2.035,3.175) 6(2.035,3.175) 7(-2.035,1.905) 8(2.035,1.905) 9(-2.035,0.635) 10(2.035,0.635) 11(-2.035,-0.635) 12(2.035,-0.635) 13(-2.035,-1.905) 14(2.035,-1.905) 15(-2.035,-3.175) 16(2.035,-3.175) 17(-2.035,-4.445) 18(2.035,-4.445) 19(-2.035,-5.715) 20(2.035,-5.715)
  silkscreen extent -1.71,-6.35 1.71,6.7, body extent -2.92,-6.35 2.92,6.35, height 6.12
SAMTEC_TMS-101-02-T-S [mm] "SAMTEC"
  rect 1.15x1.15 hole 0.66: 1(0,0)
  silkscreen extent -0.25,-1.14 0.25,1.14, body extent -0.63,-1.14 0.63,1.14, height 5.08
SO-8 [mm] "SOIC, 8-Leads, Body 5.0x4.0mm (max), Pitch 1.27mm, IPC Medium Density"
  rrect50% 2.2x0.6 smd: 1(-2.4,1.905) 2(-2.4,0.635) 3(-2.4,-0.635) 4(-2.4,-1.905) 5(2.4,-1.905) 6(2.4,-0.635) 7(2.4,0.635) 8(2.4,1.905)
  silkscreen extent -2.52,-2.5 0.9,2.88, body extent -3,-2.45 3,2.45, height 1.59
SW_1825115-1 [mm] "TH, 3-Leads, Body 433x220mil, Pitch 126mil"
  rect 1.6x1.6 hole 1.067: 1(-3.2,0)
  round 1.6 hole 1.067: 2(0,0) 3(3.2,0)
  silkscreen extent -5.5,-2.79 5.5,3.1, body extent -5.5,-2.79 5.5,2.79, height 10.36
SW_SKRKAEE010 [mm] "Alps recommended land pattern"
  rect 0.8x2 smd: 1(-2.1,0) 2(2.1,0)
  silkscreen extent -1.9,-1.44 1.92,1.44, body extent -2.4,-1.45 2.4,1.45, height 1.96
TE_1734354-1 [mm] "Receptacle, D-Sub, 9 Position, R/A, TH"
  rect 1.6x1.6 hole 1.09: 1(-10.92,5.54)
  round 1.6 hole 1.09: 2(-10.92,2.77) 3(-10.92,0) 4(-10.92,-2.77) 5(-10.92,-5.54) 6(-8.08,4.155) 7(-8.08,1.385) 8(-8.08,-1.385) 9(-8.08,-4.155)
  round 3.7 hole 3.18: 10(-9.5,12.495) 11(-9.5,-12.495)
  silkscreen extent -12.68,-15.4 -0.43,15.4, body extent -12.4,-15.4 6.02,15.4, height 12.5
TE_1981568-1 [mm] "TE Connectivity"
  rect 0.4x1.35 smd: 1(-1.3,4.225) 2(-0.65,4.225) 3(0,4.225) 4(0.65,4.225) 5(1.3,4.225)
  rect 1.6x1.4 smd: 6(-3.2,4) 7(3.2,4)
  rect 1.45x1.3 smd: 8(-3.425,1.55) 11(3.425,1.55)
  rect 1.9x1.9 smd: 9(-1.2,1.55) 10(1.2,1.55)
  silkscreen extent -3.95,-1.1 4.05,5.12, body extent -3.98,-1.12 4.02,4.48, height 2.79
TI_Stacked_Overlay_Small [mil]
  silkscreen extent -418,-98 418,98
TSW-102-07-G-S [mm] "Samtec 100mil, 1x2, 230 mil above insulator"
  rect 1.65x1.65 hole 1.016 mask+0: 1(-1.27,0)
  round 1.65 hole 1.016 mask+0: 2(1.27,0)
  silkscreen extent -2.54,-1.27 2.54,1.65, body extent -2.54,-1.27 2.54,1.27, height 8.38
TSW-103-07-G-D [mm] "Samtec 100mil, 2x3, 230 mil above insulator"
  rect 1.65x1.65 hole 1.016: 1(-2.54,-1.27)
  round 1.65 hole 1.016: 2(-2.54,1.27) 3(0,-1.27) 4(0,1.27) 5(2.54,-1.27) 6(2.54,1.27)
  silkscreen extent -4.84,-2.54 3.81,2.54, body extent -3.81,-2.54 3.81,2.54, height 8.38

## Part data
C1 C3 C4 C5 C6 C7 C8 C9 C10 C11 C12 C13 C14 C19 C26 C35 C36 C37 C38: "CAP, CERM, 0.1 µF, 16 V, +/- 10%, X7R, 0402"
C2 C18: "CAP, CERM, 1 µF, 16 V, +/- 10%, X5R, 0402"
C15 C16: "CAP, CERM, 0.01 µF, 16 V, +/- 10%, X7R, 0402"
C17: "CAP, CERM, 2.2 µF, 16 V, +/- 10%, X5R, 0402"
C20 C21: "CAP, CERM, 22 pF, 50 V, +/- 5%, C0G/NP0, 0402"
C22 C28 C29: "CAP, CERM, 0.1 µF, 25 V, +/- 5%, X7R, 0603"
C23 C24: "CAP, CERM, 0.1 µF, 16 V, +/- 10%, X7R, 0603"
C25: "CAP, CERM, 2.2 µF, 16 V, +/- 10%, X5R, 0603"
C27: "CAP, CERM, 3300 pF, 50 V, +/- 10%, X7R, 0603"
C30 C31 C33 C34: "CAP, CERM, 0.1 µF, 6.3 V, +/- 10%, X5R, 0402"
C32: "CAP, CERM, 0.1 µF, 25 V, +/- 10%, X7R, 0805"
C39 C52: "CAP, CERM, 4700 pF, 2000 V, +/- 10%, X7R, 1812"
C40 C41 C42 C43 C45 C47 C51: "CAP, CERM, 0.1 µF, 50 V, +/- 10%, X7R, 0603"
C44 C46: "CAP, CERM, 4.7 µF, 10 V, +/- 20%, X7R, 0805"
C48 C49: "CAP, CERM, 15 pF, 50 V, +/- 5%, C0G/NP0, 0603"
C50: "CAP, CERM, 1 µF, 10 V, +/- 10%, X7R, 0603"
D1 D2 D3: "LED, Green, SMD"
D4: "Diode, TVS, Uni, 2.8 V, 400 W, SO-8"
FB1 FB2: "Ferrite Bead, 120 ohm @ 100 MHz, 0.5 A, 0603"
FID1 FID2 FID3: "Fiducial mark.  There is nothing to buy or mount."
J1: "Header, 100mil, 2x1, Gold, TH"
J2 J4: "Header (Shrouded), 1.27mm, 10x2, Tin, SMT"
J3: "Header, 1.27mm, 5x2, Gold, Black, SMT"
J5: "Receptacle, D-Sub, 9 Position, R/A, TH"
J6: "Modular Connector, Jack, 4P4C, Gold, TH"
J7: "Header, 2.54mm, 10x2, Gold, SMT"
J8: "CONN DB9 FEMALE R/A SOLDER TH"
J9: "Connector, RJ-45 with integrated magnetics, 1x1, Gold, R/A, TH"
J10: "Connector, Receptacle, Micro-USB Type B, R/A, Bottom Mount SMT"
J11: "Header, 100mil, 3x2, Gold, TH"
Logo1: library part TI_Logo, "Texas Instrument Corporate Signature"
Logo2: library part Pb-Free
R1: "RES, 51, 5%, 0.1 W, 0603"
R2: "RES, 0, 5%, 0.063 W, 0402"
R3: "RES, 4.87 k, 1%, 0.063 W, 0402"
R4 R23 R25: "RES, 100, 5%, 0.063 W, 0402"
R5 R24 R26: "RES, 10 k, 5%, 0.063 W, 0402"
R6: "RES, 100 k, 1%, 0.1 W, 0402"
R7 R21 R22 R32 R33: "RES, 330, 5%, 0.1 W, 0603"
R8 R9: "RES, 4.7 k, 5%, 0.1 W, 0603"
R10: "RES, 100, 5%, 0.1 W, 0603"
R11 R12 R13 R14: "RES, 33, 5%, 0.1 W, 0603"
R15 R16 R17 R18 R27 R40 R41 R42 R43: "RES, 10 k, 5%, 0.1 W, 0603"
R19: "RES, 120, 1%, 0.1 W, 0603"
R20 R36: "RES, 1.0 M, 5%, 0.1 W, 0603"
R28 R29 R30 R31: "RES, 49.9, 1%, 0.063 W, 0402"
R34 R44: "RES, 1.0 M, 5%, 0.25 W, 1206"
R35 R39: "RES, 10.0 k, 1%, 0.1 W, 0603"
R37: "RES, 820, 1%, 0.1 W, 0603"
R38: "RES, 12.0 k, 1%, 0.1 W, 0603"
S1 S2 S3: "Switch, Push Button, SMD"
S4: "Switch, SPDT, On-On, 2 Pos, TH"
TP1 TP2 TP3 TP4: "Header, 1x1, Tin, TH"
U1: "Tiva C Series Microcontroller, PDT0128A"
U2: "Single Output LDO, 1 A, Fixed 3.3 V Output, 2.2 to 5.5 V Input, with Reverse Current Protection, 6-pin SOT-223 (DCQ), -40 to 125 degC, Green (RoHS & no Sb/Br)"
U3: "High-Speed EMC Optimized CAN Transceiver, 70 mA, 5 V, -40 to 125 degC, 8-pin SOIC (D), Green (RoHS & no Sb/Br)"
U4: "3-V to 5.5-V Multichannel RS-232 Line Driver / Receiver with ±15-kV ESD Protection, 0 to 70 degC, 16-Pin TSSOP (PW), Green (RoHS & no Sb/Br)"
U5: "DUAL CHANNEL HIGH SPEED ESD PROTECTION DEVICE, DRL0005A"
U6: "Hi-Speed USB Host, Device or OTG PHY with ULPI Low Pin Interface, QFN-32"
U7: "High-Speed USB 2.0 (480 Mbps) 1:2 Multiplexer / Demultiplexer Switch with Single Enable, 6 ohm RON, 2.5 to 3.3V, -40 to 85 degC, 10-Pin UQFN (RSE), Green (RoHS & no Sb/Br)"
U8: "6-BIT BIDIRECTIONAL VOLTAGE-LEVEL TRANSLATOR WITH AUTO-DIRECTION SENSING AND ±15-kV ESD PROTECTION, PW0016A"
Y1: "Crystal, 25MHz,  SMD"
Y2: "Crystal, 24MHz,  SMD"

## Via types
v1: diameter 22, hole 10, Component Side to Solder Side, 140 vias
v2: diameter 20, hole 8, Component Side to Solder Side, 139 vias
v3: diameter 19.68, hole 8, Component Side to Solder Side, 16 vias

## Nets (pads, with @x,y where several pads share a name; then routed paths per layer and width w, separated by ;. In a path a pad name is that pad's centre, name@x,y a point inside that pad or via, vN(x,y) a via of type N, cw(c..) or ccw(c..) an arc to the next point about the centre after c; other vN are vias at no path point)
AIN0: J2.16 U1.12 | length 1116.5
  Component Side w6: v1(2160,2900) 2315,3055 J2.16@2315,3149.88 J2.16@2315,3162.5 ; v1(2250,2250) 2280.87,2280.87 U1.12@2280.87,2323.15
  Solder Side w6: v1(2160,2900) 2140,2880 2140,2360 v1(2250,2250)
AIN1: J2.15 U1.13 | length 1030.1
  Component Side w6: U1.13@2265.12,2323.15 2263,2325.27 2263,2600 2340,2677 v1(2340,2900) ; J2.15@2315,3310.12 2315,3235 v1(2320,3230)
  Solder Side w6: v1(2320,3230) 2340,3210 v1(2340,2900)
AIN2: J2.18 U1.14 | length 845.6
  Component Side w6: U1.14@2249.37,2323.15 2249.37,2610.5 2280,2641.13 v1(2280,2850) ; J2.18@2265,3149.88 2265,3075 v1(2280,3060)
  Solder Side w6: v1(2280,2850) v1(2280,3060)
AIN3: J2.17 U1.15 | length 1327
  Component Side w6: U1.15@2233.62,2323.15 2233.62,2351 2237,2354.38 v1(2237,2769) ; v1(2238,3230) 2250,3230 2265,3245 J2.17@2265,3310.12
  Solder Side w6: v1(2237,2769) 2237,3229 v1(2238,3230) 2238,2910
CAN1RX: U1.95 U3.4 | length 1936.8
  Component Side w6: U3.4@1163.35,925 1295,925 1668.14,1298.14 1668.14,1460 2118.14,1910 2380,1910 2438.35,1851.65 U1.95@2438.35,1716.85
CAN1TX: U1.96 U3.1 | length 2317.4
  Component Side w6: U3.1@1163.35,775 1105,775 1050,830 1050,940 1120,1010 1364.44,1010 1657.14,1302.7 1657.14,1464.56 2113.59,1921 2384.56,1921 2401.85,1903.71 2406.29,1903.71 2454.09,1855.91 U1.96@2454.09,1716.85
CAN_H: J5.7 J6.2 R19.1 U3.7 | length 1541.5
  Component Side w6: U3.7@956.65,825 895,825 888.5,818.5 R19.1@830,818.5 798.5,850 635.2,850 J6.2@630,844.8 580,794.8 580,560 899,241 1125.44,241 1178.06,293.61 1178.06,350 1169.03,359.03 1169.03,360 1160,360 1134.53,334.53 J5.7@1134.53,318.11 J5.7@1129,323.64
CAN_L: J5.2 J6.3 R19.2 U3.6 | length 1716.8
  Component Side w6: U3.6@956.65,875 836.5,875 R19.2@830,881.5 809.5,861 680.5,861 660,881.5 591.5,881.5 580,870 580,844.8 J6.3@530,794.8 564.2,794.8 569,790 569,555.44 894.44,230 1130,230 1189.06,289.06 1189.06,354.56 1180.03,363.58 1180.03,364.56 1160,384.58 1160,400.87 J5.2@1189.06,429.92
E_SHIELD: C39.1 J9.13 J9.14 R34.2 | length 398.9
  Component Side w6: v2(440,1340) 441.26,1338.74 C39.1@540,1338.74 ; v2(540,1400) C39.1@540,1338.74 ; C39.1@544.88,1343.62 C39.1@540,1338.74 ; v2(760,1360) 737.09,1337.09 R34.2@680,1337.09 678.35,1338.74 C39.1@540,1338.74
ENETLED0: J9.12 U1.63 | length 1824.1
  Component Side w6: J9.12@286.73,1630.98 286.73,1553.27 320,1520 630,1520 680,1570 1609.56,1570 1831.21,1791.65 U1.63@1906.85,1791.65
ENETLED1: J9.9 U1.61 | length 2092.7
  Component Side w6: J9.9@226.89,2129.02 260.98,2129.02 330,2060 330,1900 639,1591 1601,1591 1833.15,1823.15 U1.61@1906.85,1823.15
EPHYRX_N: D4.1 D4.8 J9.6 R31.1 U1.53 | length 1779.1
  Component Side w6: 1860,1949.13 U1.53@1906.85,1949.13
  Component Side w11: J9.6@764.8,1800 J9.6@769.8,1805 769.8,1830.2 730,1870 708.63,1870 685.57,1893.06 654.04,1893.06 620,1859.02 620,1840 650.94,1809.06 692.19,1809.06 723.86,1777.39 723.86,1761.31 808.69,1761.31 835.31,1787.94 835.31,1899.94 913.37,1978 939.7,1978 956.7,1995 D4.1@1005.51,1995 1054.32,1995 1071.32,1978 1128.68,1978 1145.68,1995 D4.8@1194.49,1995 1243.3,1995 1260.3,1978 1383.97,1978 1400.35,1994.38 R31.1@1460,1994.38 1477.31,1994.38 1522.55,1949.13 1860,1949.13
EPHYRX_P: D4.2 D4.7 J9.3 R30.1 U1.54 | length 1840.7
  Component Side w6: 1860,1933.13 1906.85,1933.13 U1.54@1906.85,1933.39
  Component Side w11: J9.3@669.8,1936.2 J9.3@669.8,1955 730,1894.8 730,1890 726,1886 715.25,1886 692.19,1909.06 647.41,1909.06 604,1865.65 604,1833.37 644.31,1793.06 685.57,1793.06 707.86,1770.76 707.86,1754.69 717.23,1745.31 815.31,1745.31 851.31,1781.31 851.31,1893.31 920,1962 939.7,1962 956.7,1945 D4.2@1005.51,1945 1054.32,1945 1071.32,1962 1128.68,1962 1145.68,1945 D4.7@1194.49,1945 1243.3,1945 1260.3,1962 1392.31,1962 1392.69,1961.62 R30.1@1410,1961.62 1487.44,1961.62 1515.93,1933.13 1860,1933.13
EPHYTX_N: D4.3 D4.6 J9.2 R29.1 U1.56 | length 2500.7
  Component Side w6: 1861.89,1901.89 U1.56@1906.85,1901.89
  Component Side w11: J9.2@757.56,2012.44 750.5,2019.5 736.13,2019.5 726.63,2010 726.63,1973.37 740,1960 790,1960 820,1990 820,2080 770,2130 600,2130 580,2110 580,1700 620,1660 820,1660 872,1712 872,1836.63 913.37,1878 939.7,1878 956.7,1895 D4.3@1005.51,1895 1054.32,1895 1071.32,1878 1128.68,1878 1145.68,1895 D4.6@1194.49,1895 1243.3,1895 1260.3,1878 1436.31,1878 1442.69,1884.38 R29.1@1460,1884.38 1480.61,1884.38 1490,1874.99 1604.99,1874.99 1631.89,1901.89 1855.26,1901.89
EPHYTX_P: D4.4 D4.5 J9.1 R28.1 U1.57 | length 2694.1
  Component Side w6: 1860,1885.89 1906.85,1885.89 U1.57@1906.85,1886.14
  Component Side w11: J9.1@669.8,2055 705,2055 720,2040 720,2026 710.63,2016.63 710.63,1973.37 710.63,1966.75 733.37,1944 796.63,1944 836,1983.37 836,2086.63 776.63,2146 593.37,2146 564,2116.63 564,1839.37 564,1693.37 613.37,1644 826.63,1644 888,1705.37 888,1830 920,1862 939.7,1862 956.7,1845 D4.4@1005.51,1845 1054.32,1845 1071.32,1862 1128.68,1862 1145.68,1845 D4.5@1194.49,1845 1243.3,1845 1260.3,1862 1382.31,1862 1392.69,1851.62 R28.1@1410,1851.62 1435.61,1851.62 1442.98,1858.99 1443.84,1858.13 1476.16,1858.13 1477.02,1858.99 1611.62,1858.99 1638.52,1885.89 1860,1885.89
GND: C1.2 C2.2 C3.2 C4.2 C5.2 C6.2 C7.2 C8.2 C9.2 C10.2 C11.2 C12.2 C13.2 C14.2 C15.2 C16.2 C17.2 C18.2 C19.2 C20.2 C21.2 C22.2 C23.2 C24.2 C25.2 C26.2 C27.2 C28.2 C29.2 C32.1 C33.2 C34.2 C35.2 C36.2 C37.2 C38.2 C39.2 C40.2 C41.2 C42.2 C43.2 C44.2 C45.2 C46.2 C47.2 C48.2 C49.2 C50.2 C51.1 C52.2 FB2.2 J2.10 J2.12 J2.14 J2.19 J2.20 J3.3 J3.5 J3.9 J4.3 J4.5 J4.9 J4.11 J4.13 J4.15 J4.17 J4.19 J5.3 J6.4 J7.4 J7.6 J7.8 J7.10 J7.12 J7.14 J7.16 J7.18 J7.20 J8.5 J9.8 R3.1 R7.2 R17.1 R18.1 R20.1 R21.2 R22.2 R32.2 R33.2 R34.1 R38.1 R39.1 R40.1 R42.2 R44.1 S1.1 S2.1 S3.1 TP2.1 TP3.1 TP4.1 U1.10 U1.17 U1.48 U1.55 U1.58 U1.64 U1.66 U1.80 U1.114 U2.3 U2.6 U3.2 U4.15 U6.1 U6.2 U6.33 U7.5 U8.9 | length 8458.2
  Component Side w6: v1(140,1150) 141.5,1148.5 R33.2@190,1148.5 ; R32.2@260,1148.5 v1(310,1148.5) v1@318.5,1148.5 ; v1(440,1180) 441.26,1181.26 C39.2@540,1181.26 ; J6.4@630,744.8 664.8,744.8 v1(690,770) ; v1(680,1170) R34.1@680,1222.91 ; v1(690,640) 691.5,641.5 C27.2@741.46,641.5 C27.2@741.46,641 ; v2(790,2750) C33.2@836.38,2750 ; R20.1@811.46,641 R20.1@811.46,641.5 858.5,641.5 v1(860,640) ; C32.1@860,2950 v2(860,3000) ; R18.1@1021.5,680 v2(1070,680) ; C37.2@1073.62,2170 v2(1120,2170) ; v1(1114.54,1206.99) 1128.19,1220.63 S1.1@1128.19,1247.32 ; U3.2@1163.35,825 1215,825 v2(1230,810) ; U4.15@1196.14,2873.98 1236.02,2873.98 v2(1250,2860) 1253.62,2856.38 C34.2@1290,2856.38 ; v2(1229.83,2405.28) R22.2@1278.33,2405.28 ; v2(1229.83,2545.28) R21.2@1278.33,2545.28 ; v1(1290,1660) C38.2@1290,1706.38 ; C36.2@1322,2090 C36.2@1326.38,2090 1326.38,2052.38 v1(1324,2050) ; C22.2@1388.19,1491.5 v1(1388.19,1540) ; C35.2@1513.62,1790 v2(1560,1790) ; v1(1670,2000) 1686,1984 C8.2@1716.38,1984 ; v1(1670,2050) 1686,2034 C16.2@1716.38,2034 ; v1(1670,2100) 1686,2084 C6.2@1716.38,2084 ; v1(1670,2190) C9.2@1716.38,2190 C9.2@1729,2190 ; v1(1680,1840) R3.1@1736.38,1840 ; v2(1700,3030) C29.2@1751.51,3030 ; v2(1720,710) C25.2@1768.5,710 1768.5,678.5 v2(1750,660) ; v1(1770,510) C26.2@1770,556.38 1796.38,556.38 v2(1810,570) ; S3.1@1770,3342.68 v2(1770,3380) ; v2(1810,450) 1811.5,451.5 C23.2@1867.01,451.5 1867.01,417.01 v1(1850,400) ; v1(1840,1860) 1850.39,1870.39 U1.58@1906.85,1870.39 ; v1(1863.29,1763.41) 1875.79,1775.91 U1.64@1906.85,1775.91 ; v1(1867.5,1450.5) C1.2@1915.16,1450.5 1915.16,1485.16 v2(1930,1500) ; U1.55@1906.85,1917.64 1977.64,1917.64 v1(1980,1920) ; U1.48@1906.85,2027.87 1977.87,2027.87 v1(1980,2030) ; v2(1930,840) 1930.2,840.2 U2.6@2029.49,840.2 ; v2(1930,920) v2(2030,920) ; S2.1@1940,3342.68 v2(1940,3380) ; v1(1981.65,1673.29) U1.66@1981.65,1716.85 ; v1(2000,2570) 2010,2560 C7.2@2010,2523.62 C7.2@2010,2523 ; C28.2@2004.5,2963.99 2033.99,2963.99 v1(2050,2980) ; v1(2030,540) 2029.49,540.51 U2.3@2029.49,605.95 2029.49,689.49 v2(2030,690) ; v1(2030,1480) C12.2@2030,1526.38 C12.2@2030,1530 ; v1(2080,1590) C13.2@2126.38,1590 ; C4.2@2080,2523 C4.2@2080,2523.62 v1(2080,2570) ; v2(2130,840) 2129.8,840.2 U2.6@2029.49,840.2 ; v2(2130,920) v2(2030,920) ; v1(2170,3150) 2170.12,3149.88 J2.20@2215,3149.88 J2.19@2215,3297.5 ; v1(2170,3310) 2170.12,3310.12 J2.19@2215,3310.12 ; v1(2180,2390) 2202.13,2367.87 U1.17@2202.13,2323.15 ; v2(2200,1460) C20.2@2246.38,1460 ; U1.80@2202.13,1716.85 2202.13,1772.13 v1(2220,1790) ; C5.2@2210,2523 C5.2@2210,2523.62 v1(2210,2570) ; C2.2@2290,2523 C2.2@2290,2523.62 v1(2290,2590) ; v2(2300,960) 2310.99,970.99 R7.2@2310.99,1013.08 2333.08,1013.08 v1(2360,1040) ; U1.10@2312.36,2323.15 2312.36,2257.64 v1(2320,2250) ; v2(2340,660) 2321.5,678.5 C24.2@2321.5,710 v1(2370,710) ; C3.2@2340,2523 C3.2@2340,2523.62 v1(2340,2580) ; J2.14@2365,3149.88 2365,3215 v1(2380,3230) ; C15.2@2390,2523 C15.2@2390,2523.62 v1(2390,2570) ; v2(2400,3060) 2415,3075 J2.12@2415,3149.88 ; C21.2@2403.62,1460 v2(2450,1460) ; v2(2450,3060) 2465,3075 J2.10@2465,3149.88 ; U1.114@2513.15,2043.62 2566.38,2043.62 v1(2580,2030) ; v1(2540,390) C50.2@2598.5,390 ; v1(2580,540) R38.1@2628.5,540 2648.5,540 2649,540.5 2649,554.5 ; C14.2@2723.62,1840 v1(2770,1840) ; C10.2@2723.62,2190 v1(2780,2190) ; v2(2760.2,560.2) C47.2@2760.2,607.01 ; v2(2770,740) C48.2@2770,788.5 ; C49.2@2770,981.5 v2(2770,1030) ; v1(2780,2010) C11.2@2723.62,2010 2717,2010 2717,2060 C18.2@2720,2060 ; v1(2780,2060) C18.2@2723.62,2060 C18.2@2720,2060 ; v1(2780,2110) C17.2@2723.62,2110 2720,2110 C18.2@2720,2060 ; v1(2820,340) 2840,360 R40.1@2878.5,360 ; C46.2@2830.2,630 C46.2@2830.2,639 ; v2(2840,560) C46.2@2840,620 ; v2(2840,2660) 2863.86,2683.86 U8.9@2880.43,2683.86 ; C44.2@2850,1060 2850,1100 ; v2(2850,1120) 2850,1100 ; C44.2@2850.2,1047.64 C44.2@2850.2,1060 ; C44.2@2850.2,1076 2850.2,1099.8 2850,1100 ; v2(2920,590) C43.2@2920,638.5 ; v1(2920,1130) 2920.2,1129.8 C42.2@2920.2,1077.64 ; v2(2960,3257.5) J7.4@2960,3330 ; v1(2980,410) 2990,400 U7.5@3024.57,400 ; v2(2980,710) 2981.1,711.1 U6.1@2981.1,761.69 ; U6.2@3000.79,761.69 3000.79,709.21 v2(3020,690) ; v2(3060,3257.5) J7.6@3060,3330 ; v1(3140,2800) J3.3@3229.88,2800 ; v2(3160,1160) 3160.2,1159.8 C41.2@3160.2,1099 ; v2(3160,3257.5) J7.8@3160,3330 ; J3.9@3229.88,2650 3229.88,2600.12 v1(3230,2600) ; J3.5@3229.88,2750 3290,2750 v1(3310,2770) ; C45.2@3230,1001.5 v1(3230,1050) ; v2(3240,2190) R17.1@3298.5,2190 ; v2@3260,3250 v2(3260,3257.5) J7.10@3260,3330 ; v2(3300,270) 3301.5,271.5 FB2.2@3301.5,320 v2(3350,320) ; C51.1@3301.5,420 v2(3350,420) ; v2(3310,520) R42.2@3358.5,520 ; C40.2@3321.5,700 v2(3370,700) ; v2(3360,3257.5) J7.12@3360,3330 ; R39.1@3431,786.14 R39.1@3431.69,786.14 v2(3486.14,786.14) v2@3490,790 ; v2(3460,3257.5) J7.14@3460,3330 ; v2(3490,2730) 3584.88,2730 J4.5@3589.88,2725 ; v2(3490,2780) 3584.88,2780 J4.3@3589.88,2775 ; v2(3500,2360) 3515,2375 J4.19@3589.88,2375 ; v2(3500,2410) 3515,2425 J4.17@3589.88,2425 ; v2(3500,2460) 3515,2475 J4.15@3589.88,2475 ; v2(3500,2510) 3515,2525 J4.13@3589.88,2525 ; v2(3500,2560) 3515,2575 J4.11@3589.88,2575 ; v2(3500,2610) 3515,2625 J4.9@3589.88,2625 ; v2(3550,340) 3537.09,327.09 R44.1@3537.09,270 3590,270 v2(3600,280) ; v2(3560,3257.5) J7.16@3560,3330 ; v2(3600,230) 3578.74,208.74 C52.2@3578.74,130 v2(3650,130) ; v2(3660,3257.5) J7.18@3660,3330 ; v2(3760,3257.5) J7.20@3760,3330 ; U2.6@2029.49,840.2 2029.49,919.49 v2(2030,920)
  Solder Side w6: J9.8@769.8,1705 865,1705 v2(950,1620) ; v2(2220,1840) C19.2@2266.38,1840
  other v3: 2996.85,802.85 3032.28,802.85 3067.72,802.85 3103.15,802.85 2996.85,838.28 3032.28,838.28 3067.72,838.28 3103.15,838.28 2996.85,873.72 3032.28,873.72 3067.72,873.72 3103.15,873.72 2996.85,909.15 3032.28,909.15 3067.72,909.15 3103.15,909.15
GPIOLED1: D2.1 U1.31 | length 503.1
  Component Side w6: D2.1@1591.17,2545.28 1794.72,2545.28 1981.65,2358.35 U1.31@1981.65,2323.15
GPIOLED2: D3.1 U1.32 | length 428.9
  Component Side w6: D3.1@1591.17,2405.28 1918.22,2405.28 1965.91,2357.59 U1.32@1965.91,2323.15
GPIOSW1: C28.1 R23.1 R24.1 U1.22 | length 824.7
  Component Side w6: v2(1940,2860) 1940,2903.37 R24.1@1939.38,2903.99 1939.38,2961.86 C28.1@1941.51,2963.99 1943,2963.99 R23.1@1943,3040.36 ; v2(2110,2730) 2130,2710 2130,2400 2123.39,2393.39 U1.22@2123.39,2323.15
  Solder Side w6: v2(1940,2860) 2070,2730 v2(2110,2730)
GPIOSW2: C29.1 R25.1 R26.1 U1.23 | length 948.1
  Component Side w6: R25.1@1813.62,3110 1813.62,3030.88 C29.1@1814.5,3030 1814.5,2970.88 R26.1@1813.62,2970 1813.62,2926.38 v2(1830,2910) ; v2(2090,2700) 2119,2671 2119,2420 2107.64,2408.64 U1.23@2107.64,2323.15
  Solder Side w6: v2(1830,2910) 2040,2700 v2(2090,2700)
I2C1SCL: J2.13 R9.1 U1.49 | length 1985.1
  Component Side w6: v1(1840,2030) 1857.87,2012.13 U1.49@1906.85,2012.13 ; v2(1920,2620) 1920,2730 1908.54,2741.46 R9.1@1871.5,2741.46 1871.5,2790.5 1880,2799 2025,2799 2131,2905 2131,3355.44 2164.56,3389 2350,3389 2365,3374 J2.13@2365,3310.12
  Solder Side w6: v1(1840,2030) 1840,2540 v2(1920,2620)
I2C1SDA: J2.11 R8.1 U1.50 | length 2081.8
  Component Side w6: v1(1810,2050) 1810,2033.13 1846.75,1996.38 U1.50@1906.85,1996.38 ; v2(1830,2580) 1870,2620 1870,2669.96 R8.1@1871.5,2671.46 1848.54,2671.46 1840,2680 1840,2780 1870,2810 2020.44,2810 2120,2909.56 2120,3360 2160,3400 2390,3400 2415,3375 J2.11@2415,3310.12
  Solder Side w6: v1(1810,2050) 1810,2163.13 1829,2182.13 1829,2579 v2(1830,2580)
JTAG_TCK: R12.2 R16.1 U1.100 | length 1514.6
  Component Side w6: U1.100@2513.15,1823.15 2616.85,1823.15 v1(2640,1800) ; R16.1@3131.49,2440 3170,2440 3180,2430 3180,2410 3190,2400 3280,2400 3290,2390 R12.2@3290,2368.5 3290,2313 3200,2223 v2(3200,1800)
  Solder Side w6: v1(2640,1800) v2(3200,1800)
JTAG_TDI: R14.2 U1.98 | length 1421.3
  Component Side w6: U1.98@2513.15,1791.65 2568.35,1791.65 v1(2600,1760) ; v1(3230,1760) 3230,1784.44 3241,1795.44 3241,1981 3430,2170 R14.2@3430,2368.5
  Solder Side w6: v1(2600,1760) v1(3230,1760)
JTAG_TDO: R13.2 R17.2 U1.97 | length 1378.9
  Component Side w6: U1.97@2513.15,1775.91 2544.09,1775.91 v1(2580,1740) ; v2(3170,1740) 3230,1800 3230,2019.58 3360,2149.58 R13.2@3360,2368.5
  Solder Side w6: v1(2580,1740) v2(3170,1740)
JTAG_TMS: R11.2 R15.1 U1.99 | length 1372.4
  Component Side w6: U1.99@2513.15,1807.4 2592.6,1807.4 v1(2620,1780) ; R15.1@3131.49,2370 3218.5,2370 R11.2@3220,2368.5 3220,2302 3180,2262 v2(3180,1780)
  Solder Side w6: v1(2620,1780) v2(3180,1780)
MCU_GPIO0: U1.1 U8.16 | length 834.5
  Component Side w6: U1.1@2454.09,2323.15 2454.09,2354.09 2460.56,2360.55 v2(2500,2360.55) ; U8.16@3059.57,2683.86 3059.57,2580.43 v2(3060,2580)
  Solder Side w6: v2(2500,2360.55) 2800.55,2360.55 3000,2560 3040,2560 v2(3060,2580)
MCU_GPIO1: U1.2 U8.14 | length 799.3
  Component Side w6: U1.2@2438.35,2323.15 2438.35,2357.23 2471.11,2390 v2(2500,2390) ; U8.14@3008.39,2683.86 3010,2682.24 v2(3010,2630)
  Solder Side w6: v2(2500,2390) 2814.44,2390 3010,2585.56 v2(3010,2630)
MCU_GPIO2: U1.3 U8.13 | length 793.9
  Component Side w6: U1.3@2422.6,2323.15 2422.6,2357.04 2485.56,2420 v2(2500,2420) ; v2(2970,2590) 2982.8,2602.8 U8.13@2982.8,2683.86
  Solder Side w6: v2(2500,2420) 2828.89,2420 2970,2561.11 v2(2970,2590)
MCU_GPIO3: U1.4 U8.12 | length 789.8
  Component Side w6: U1.4@2406.85,2323.15 2406.85,2356.85 v2(2500,2450) ; v2(2910,2560) 2957.2,2607.2 U8.12@2957.2,2683.86
  Solder Side w6: v2(2500,2450) 2843.33,2450 2910,2516.67 v2(2910,2560)
MCU_GPIO4: U1.107 U8.11 | length 1308.8
  Component Side w6: U1.107@2513.15,1933.39 2930,1933.39 2990,1993.39 2990,2120 2820,2290 v2(2820,2490) ; v2(2930,2630) 2931.61,2631.61 U8.11@2931.61,2683.86
  Solder Side w6: v2(2820,2490) 2820,2520 v2(2930,2630)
